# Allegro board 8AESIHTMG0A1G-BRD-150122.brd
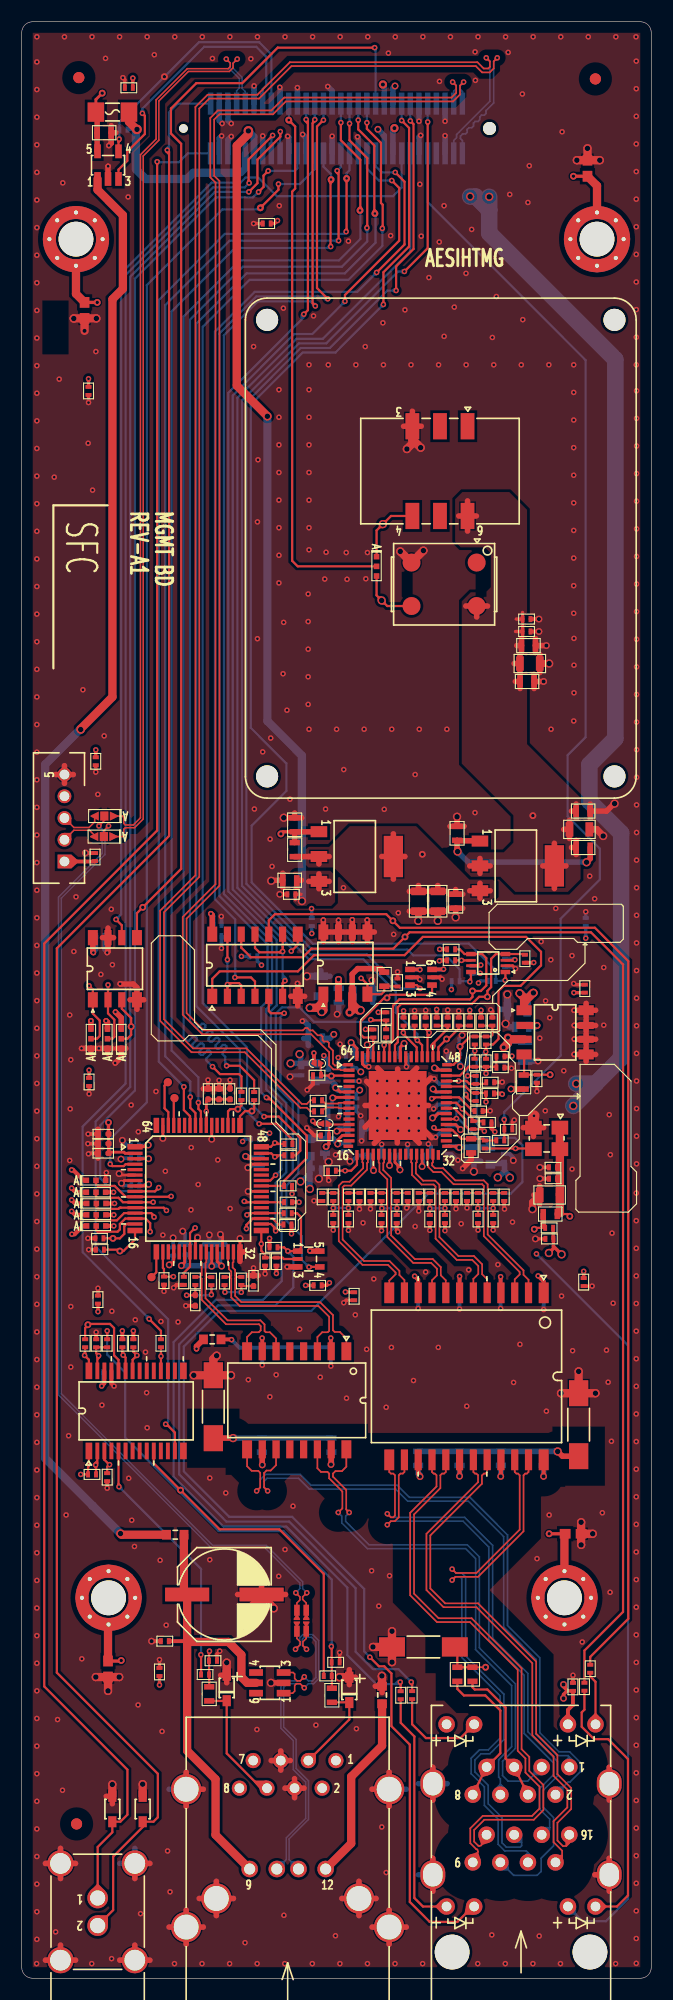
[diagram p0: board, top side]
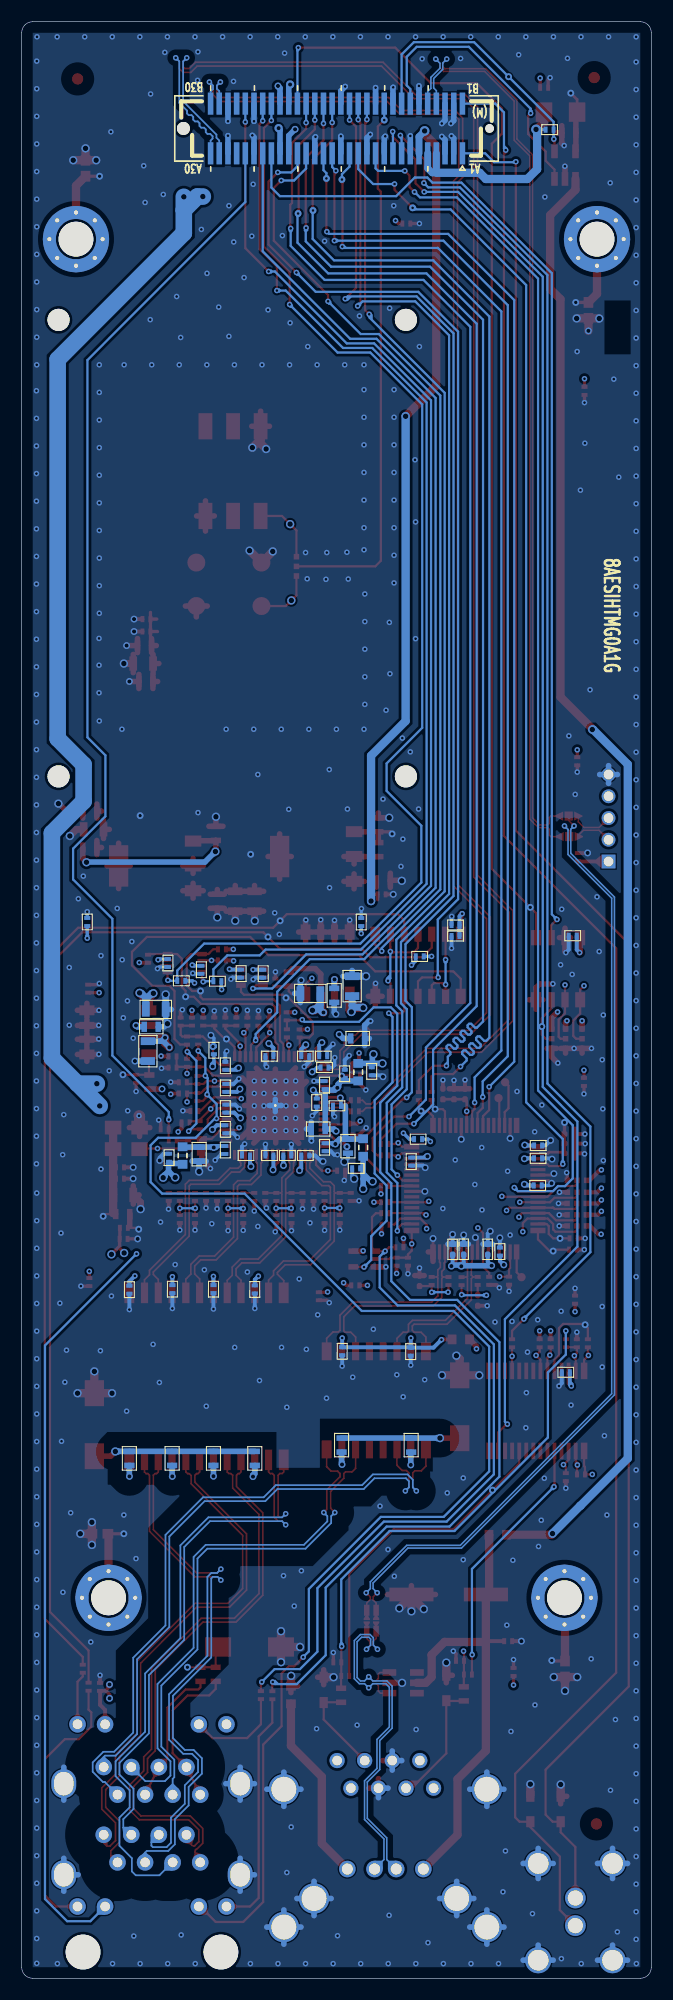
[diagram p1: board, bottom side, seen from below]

Outline 58 x 180 mm; copper layers: TOP, L2_GND, L3_VCC, BOTTOM. Coordinates in mm from the lower left corner of the outline.

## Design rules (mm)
net group RMIICRSDV: nets RMIICRSDV RMIICRSDV_R
net group RMIIRXD0: nets RMIIRXD0 RMIIRXD0_R
net group RMIIRXD1: nets RMIIRXD1 RMIIRXD1_R
net group RMIIRXER: nets RMIIRXER RMIIRXER_R
nets with their own width: min track width 0.254; nets 5V_IN

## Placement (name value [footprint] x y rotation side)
A1  3.5mm_8via  [A126_DG]  5 160 0 top
A2  3.5mm_8via  [A126_DG]  53 160 0 top
A3  3.5mm_8via  [A126_DG]  8 35 0 top
A4  3.5mm_8via  [A126_DG]  50 35 0 top
B1  Optics  [2B]  5.26 174.86 0 top
B2  Optics  [2B]  52.85 174.74 0 top
B3  Optics  [2B]  5.05 14.2 0 top
C1  1uF 6.3V  [C0402]  9.87 173.92 0 top
C2  0.1uF 16V  [C0603]  7.6 169.79 0 top
C3  0.1uF 16V***  [SJS_0603_PLANE]  52.12 166.52 90 top
C4  1uF 6.3V  [C0402]  22.57 161.43 0 top
C5  0.1uF 16V***  [SJS_0603_PLANE]  5.79 153.44 270 top
C6  1uF 6.3V  [C0402]  6.15 146.03 90 top
C7  0.1uF 16V  [C0402]  46.51 125.04 0 top
C8  0.1uF 16V  [C0402]  46.51 123.9 0 top
C9  1uF 25V  [C0603]  46.69 122.61 0 top
C10  22uF 6.3V  [C0805]  46.81 120.95 0 top
C11  0.1uF 16V  [C0603]  46.56 119.3 0 top
C12  1uF 6.3V  [C0402]  6.82 111.96 90 top
C13  0.1uF 16V  [C0603]  51.72 107.38 0 top
C14  22uF 6.3V  [C0805]  51.38 105.7 0 top
C15  0.1uF 16V  [C0402]  6.76 103.15 90 top
C16  1uF 25V  [C0603]  24.69 101.02 180 top
C17  0.1uF 16V  [C0402]  24.84 99.72 180 top
C18  22uF 6.3V  [C0805]  36.55 99.09 270 top
C19  22uF 6.3V  [C0805]  38.33 99.09 270 top
C20  0.1uF 16V  [C0603]  39.98 99.09 270 top
C21  0.1uF 16V  [C0402]  51.88 91.04 270 top
C22  100P 50V  [C0402]  36.2 88.01 90 top
C23  ***0.1uF 16V  [C0402]  27.21 83.08 0 top
C24  1uF 6.3V  [C0402]  6.21 82.46 90 top
C25  10NF 50V  [C0402-HANK]  17.16 81.35 90 top
C26  2.2UF X5R 6.3V 20%  [C0402-HANK]  18.18 81.35 90 top
C27  0.1uF 16V  [C0402-HANK]  19.2 81.35 90 top
C28  10NF 50V  [C0402]  27.3 80.77 0 top
C29  10NF 50V  [C0402]  27.3 79.76 0 top
C30  2.2UF X5R 6.3V 20%  [C0402-HANK]  7.51 77.67 180 top
C31  ***0.1uF 16V  [C0402]  27.93 77.54 0 top
C32  10NF 50V  [C0402-HANK]  7.51 76.78 180 top
C33  0.1uF 16V  [C0402-HANK]  7.51 75.89 180 top
C34  0.1uF 16V***  [C0402]  48.94 74.61 180 top
C35  1000P 50V***  [C0402]  48.95 73.56 180 top
C36  22uF 6.3V***  [C0805]  48.64 72.06 180 top
C37  ***5pF 50V  [C0402]  27.69 71.88 270 top
C38  ***5pF 50V  [C0402]  31.11 71.88 270 top
C39  ***5pF 50V  [C0402]  32.13 71.88 270 top
C40  ***5pF 50V  [C0402]  35.56 71.88 270 top
C41  ***5pF 50V  [C0402]  36.58 71.88 270 top
C42  ***5pF 50V  [C0402]  40.01 71.88 270 top
C43  ***5pF 50V  [C0402]  41.02 71.88 270 top
C44  ***5pF 50V  [C0402]  44.45 71.88 270 top
C45  ***0.1uF 16V  [C0402]  28.7 69.85 270 top
C46  10NF 50V  [C0402]  30.1 69.85 270 top
C47  ***0.1uF 16V  [C0402]  33.15 69.85 270 top
C48  10NF 50V  [C0402]  34.54 69.85 270 top
C49  10NF 50V  [C0402]  37.59 69.85 270 top
C50  ***0.1uF 16V  [C0402]  38.99 69.85 270 top
C51  ***0.1uF 16V  [C0402]  42.04 69.85 270 top
C52  10NF 50V  [C0402]  43.43 69.85 270 top
C53  0.1uF 16V***  [C0402]  48.62 68.02 180 top
C54  0.1uF 16V  [C0402-HANK]  21.35 64.17 90 top
C55  0.1uF 16V  [C0402]  51.77 64.05 90 top
C56  0.1uF 16V  [C0402]  27.27 63.75 180 top
C57  0.1uF 16V  [C0402]  30.62 62.74 90 top
C58  1uF 6.3V  [C0402]  7.02 62.43 270 top
C59  0.1uF 16V  [C0402-HANK]  15.99 62.36 270 top
C60  0.1uF 16V  [C0402]  5.84 58.42 270 top
C61  0.1uF 16V  [C0402]  6.86 58.42 270 top
C62  1000pF 3KV  [C1808_3KV]  17.65 52.58 90 top
C63  CAP 1000P/250Vac  [C1808_3KV]  51.31 50.93 90 top
C64  0.1uF 16V  [C0402]  6.48 46.35 180 top
C65  0.1uF 16V  [C0402]  7.87 46.1 90 top
C66  0.1uF 16V***  [SJS_0603_PLANE]  50.8 40.89 0 top
C67  180UF 16V  [C8P3X8P3]  18.67 35.31 0 top
C68  0.1uF 16V  [C0402]  13.18 31.01 0 top
C69  1000pF 3KV  [C1808_3KV]  37.01 30.48 0 top
C70  ***1000P 50V  [C0402]  17.62 29.21 0 top
C71  ***1000P 50V  [C0402]  28.92 29.07 0 top
C72  1uF 6.3V  [C0402]  12.69 28.18 270 top
C73  0.1uF 16V***  [SJS_0603_PLANE]  7.95 28.45 270 top
C74  0.1uF 16V  [C0402]  50.78 26.81 90 top
C75  0.1uF 16V  [C0402]  51.96 97.18 270 bottom
C76  0.1uF 16V  [C0402]  26.72 97.17 270 bottom
C77  0.1uF 16V  [C0402]  18.03 96.9 0 bottom
C78  0.1u 16V  [C0402]  7.24 95.91 180 bottom
C79  0.1uF 16V  [C0402]  18.03 95.89 0 bottom
C80  0.1uF 16V  [C0402]  21.33 94.01 180 bottom
C81  0.1uF 16V  [C0402]  44.53 93.4 270 bottom
C82  1uF 6.3V  [C0402]  41.45 92.78 270 bottom
C83  0.1uF 16V  [C0402]  37.79 92.43 270 bottom
C84  0.1uF 16V  [C0402]  35.75 92.42 270 bottom
C85  22uF 6.3V  [C0805]  27.56 91.27 90 bottom
C86  22uF 6.3V  [C0805]  31.41 90.6 0 bottom
C87  1uF 10V  [C0603]  29.21 90.42 270 bottom
C88  22uF 6.3V  [C0805]  45.65 89.13 180 bottom
C89  1uF 10V  [C0603]  46.07 87.53 180 bottom
C90  10uF 6.3V  [C0603]  27.05 86.46 180 bottom
C91  1uF 6.3V  [C0402]  40.29 85.38 90 bottom
C92  22uF 6.3V  [C0805]  46.38 85.3 270 bottom
C93  0.1uF 16V  [C0402]  35.18 84.84 0 bottom
C94  1uF 6.3V  [C0402]  31.88 84.84 180 bottom
C95  1uF 6.3V  [C0402]  30.23 84.84 180 bottom
C96  1uF 6.3V  [C0402]  39.24 83.95 90 bottom
C97  1uF 6.3V  [C0402]  30.1 83.78 180 bottom
C98  1uF 6.3V  [C0402]  25.76 83.44 270 bottom
C99  0.1uF 16V  [C0402]  28.24 83.21 90 bottom
C100  0.1uF 16V  [C0402]  30.1 82.17 90 bottom
C101  1uF 6.3V  [C0402]  39.24 81.92 90 bottom
C102  1uF 6.3V  [C0402]  30.82 80.56 270 bottom
C103  0.1uF 16V  [C0402]  28.96 80.26 0 bottom
C104  1uF 6.3V  [C0402]  39.24 80.01 90 bottom
C105  10uF 6.3V  [C0603]  30.68 78.13 0 bottom
C106  0.1uF 16V  [C0402]  39.24 78.11 270 bottom
C107  0.1uF 16V  [C0402]  21.48 77.2 180 bottom
C108  0.1uF 16V  [C0402]  10.42 76.62 0 bottom
C109  10uF 6.3V  [C0603]  27.94 76.56 270 bottom
C110  0.1uF 16V  [C0402]  30.1 76.45 270 bottom
C111  1uF 6.3V  [C0402]  39.24 76.2 270 bottom
C112  10uF 6.3V  [C0603]  41.66 75.82 270 bottom
C113  1uF 6.3V  [C0402]  37.34 75.69 0 bottom
C114  1uF 6.3V  [C0402]  35.18 75.69 0 bottom
C115  1uF 6.3V  [C0402]  33.53 75.69 180 bottom
C116  1uF 6.3V  [C0402]  31.88 75.69 180 bottom
C117  1uF 6.3V  [C0402]  44.42 75.49 90 bottom
C118  0.1uF 16V  [C0402]  10.43 75.43 0 bottom
C119  0.1uF 16V  [C0402]  22.12 75.13 90 bottom
C120  1uF 6.3V  [C0402]  27.19 74.51 0 bottom
C121  0.1uF 16V  [C0402]  10.46 72.94 0 bottom
C122  0.1uF 16V  [C0402-HANK]  17.28 67.07 90 bottom
C123  2.2UF X5R 6.3V 20%  [C0402-HANK]  15.07 67.06 90 bottom
C124  10NF 50V  [C0402-HANK]  18.3 67.06 90 bottom
C125  0.1uF 16V  [C0402]  13.95 66.85 270 bottom
C126  0.1uF 16V  [C0402]  44.12 63.4 270 bottom
C127  0.1uF 16V  [C0402]  40.34 63.4 270 bottom
C128  0.1uF 16V  [C0402]  36.53 63.37 270 bottom
C129  0.1uF 16V  [C0402]  48.08 63.35 270 bottom
C130  0.1uF 16V  [C0402]  28.48 57.68 270 bottom
C131  0.1uF 16V  [C0402]  22.16 57.65 270 bottom
C132  0.1uF 16V  [C0402]  7.87 55.75 180 bottom
D1  SRV05-4  [SOT_26]  22.86 27.18 90 top
D2  GBLC24C  [SOD_323]  18.88 26.71 270 top
D3  GBLC24C  [SOD_323]  30.18 26.53 270 top
D4  GBLC03C  [SOD_323N]  8.35 15.57 90 top
D5  GBLC03C  [SOD_323N]  11.14 15.57 90 top
F1  1.5A/63V  [FUSE_1206]  8.36 171.69 0 top
J1  33R 5% 1/16W  [JP3_0402]  32.69 129.9 270 top
J2  1K 5% 1/16W  [JP3_0402]  6.38 86.44 90 top
J3  1K 5% 1/16W  [JP3_0402]  7.9 86.44 90 top
J4  1K 5% 1/16W  [JP3_0402]  9.17 86.44 90 top
J5  1K 5% 1/16W  [JP3_0402]  6.84 73.41 0 top
J6  1K 5% 1/16W  [JP3_0402]  6.84 72.31 0 top
J7  1K 5% 1/16W  [JP3_0402]  6.87 71.28 0 top
J8  1K 5% 1/16W  [JP3_0402]  6.87 70.24 0 top
J9  1K 5% 1/16W  [JP3_0402]  6.86 69.21 0 top
J10  TE# 3-5177986-2  [C_5179029_2]  29 170.18 0 bottom
JP1  HEADER1* 5P=2.0 mm  [P200_5_2P0]  3.94 102.74 90 top
L1  40ohm/100MHZ 0.4A***  [L0603]  48.69 70.31 0 top
L2  HCB1608KF-601T10  [L2_LQW18]  17.55 58.78 0 top
L3  HCB1608KF-601T10  [L2_LQW18]  14.15 40.8 180 top
L4  BEAD 600OHM/ 100MHZ 25%  [L0603]  17.27 26.16 270 top
L5  HCB1608KF-601T10  [L2_LQW18]  33.2 26.06 270 top
L6  BEAD 600OHM/ 100MHZ 25%  [L0603]  28.57 26.04 270 top
L7  HCB1608KF-601T10  [L2_LQW18]  27 83.36 270 bottom
L8  HCB1608KF-601T10  [L2_LQW18]  26.54 76.43 90 bottom
L9  HCB1608KF-601T10  [L2_LQW18]  43.18 75.69 90 bottom
N1  0ohm  [0_OHM_3PIN]  7.61 106.92 180 top
N2  0ohm  [0_OHM_3PIN]  7.57 105.03 180 top
N3  0ohm  [0_OHM_2PIN]  27.24 84.18 180 top
N4  0ohm  [0_OHM_2PIN]  27.93 78.63 180 top
N5  0ohm***  [0_OHM_2PIN]  25.35 32.89 270 top
N6  0ohm***  [0_OHM_2PIN]  26.21 32.89 270 top
NOREF  ***  []  1.91 154.36 270 top
NOREF#2  -  []  60.71 180.09 0 top
NOREF#3  -  []  0 0 0 top
NOREF#4  -  []  2.92 135.51 270 top
NOREF#5  -  []  4.39 116.99 90 top
NOREF#6  -  []  12.27 135.13 270 top
P1  Plastic Top Cover  [OSCD5_OCXO_131_COVER]  38.61 131.57 270 top
P2  AJ-091-21-F-R4-N4-5G  [PHJ8X1X2_LED_D]  52.35 2.41 180 top
P3  PHJ8 + USB  [PHJ8_SHIE_USB_A]  31.07 7.34 0 top
P4  MiniBNC1x2 MDB-960  [BNC_MDB_960]  10.42 1.66 270 top
R1  1.1K 1% 1/10W  [R0603]  25.15 106.12 90 top
R2  392 1% 1/10W  [R0603]  40.11 105.33 90 top
R3  240 5% 1/10W  [R0603]  51.72 104.03 0 top
R4  240 5% 1/10W  [R0603]  25.15 103.84 90 top
R5  3.3K 5% 1/16W  [R0402]  39.56 94.66 0 top
R6  3.3K 5% 1/16W  [R0402]  46.36 93.8 90 top
R7  3.3K 5% 1/16W  [R0402]  39.56 93.64 180 top
R8  5.11K 1% 1/10W  [R0603]  33.4 91.92 270 top
R9  10K 1% 1/16W  [R0402]  34.62 91.61 90 top
R10  4.7K 1% 1/16W  [R0402]  33.59 88.5 270 top
R11  4.7K 1% 1/16W  [R0402]  35.18 88.01 90 top
R12  1K 1% 1/16W  [R0402]  37.21 88.01 90 top
R13  ***4.7K 1% 1/16W  [R0402]  38.23 88.01 270 top
R14  1K 1% 1/16W  [R0402]  39.24 88.01 90 top
R15  ***1K 1% 1/16W  [R0402]  40.26 88.01 90 top
R16  4.7K 1% 1/16W  [R0402]  41.27 88.01 270 top
R17  ***0ohm 5% 1/16W  [R0402]  42.32 88.01 270 top
R18  ***0ohm 5% 1/16W  [R0402]  43.36 88.01 270 top
R19  0ohm 5% 1/16W  [R0402]  33.57 86.94 90 top
R20  4.7K 1% 1/16W  [R0402]  32.39 86.92 90 top
R21  ***0ohm 5% 1/16W  [R0402]  42.77 86.27 270 top
R22  0ohm 5% 1/16W  [R0402]  41.74 86.27 270 top
R23  ***0ohm 5% 1/16W  [R0402]  44.11 84.81 180 top
R24  ***0ohm 5% 1/16W  [R0402]  41.72 84.22 90 top
R25  ***0ohm 5% 1/16W  [R0402]  42.77 84.22 90 top
R26  0ohm 5% 1/16W  [R0402]  44.1 83.78 180 top
R27  10.5K 1% 1/16W  [R0402]  47.46 82.76 270 top
R28  ***0ohm 5% 1/16W  [R0402]  41.82 82.65 90 top
R29  22.6K 1% 1/10W  [R0603]  46.24 82.45 90 top
R30  0ohm 5% 1/16W  [R0402]  43.16 82.43 180 top
R31  ***0ohm 5% 1/16W  [R0402]  43.14 81.4 180 top
R32  33 1% 1/16W  [R0402]  20.24 81.17 90 top
R33  33 1% 1/16W  [R0402]  21.41 81.16 90 top
R34  0ohm 5% 1/16W  [R0402]  41.83 81.08 270 top
R35  0ohm 5% 1/16W  [R0402]  42.09 79.78 180 top
R36  ***0ohm 5% 1/16W  [R0402]  42.91 78.74 180 top
R37  0ohm 5% 1/16W  [R0402]  41.6 78.49 270 top
R38  ***49.9 1% 1/16W  [R0402]  44.83 78.11 180 top
R39  33 1% 1/16W  [R0402]  44.09 77.09 180 top
R40  33 1% 1/16W  [R0402]  24.57 76.76 0 top
R41  33 1% 1/16W***  [R0402]  42.67 76.71 90 top
R42  220 1% 1/10W***  [R0603]  41.4 76.58 270 top
R43  33 1% 1/16W  [R0402]  24.56 75.71 0 top
R44  4.99K 1% 1/16W  [R0402]  28.57 74.3 0 top
R45  1.5K 5% 1/16W  [R0402]  24.54 72.9 0 top
R46  49.9 1% 1/16W  [R0402]  28.7 71.88 270 top
R47  49.9 1% 1/16W  [R0402]  30.1 71.88 90 top
R48  49.9 1% 1/16W  [R0402]  33.15 71.88 270 top
R49  49.9 1% 1/16W  [R0402]  34.54 71.88 90 top
R50  49.9 1% 1/16W  [R0402]  37.59 71.88 270 top
R51  49.9 1% 1/16W  [R0402]  38.99 71.88 90 top
R52  49.9 1% 1/16W  [R0402]  42.04 71.88 270 top
R53  49.9 1% 1/16W  [R0402]  43.43 71.88 90 top
R54  10K 1% 1/16W  [R0402]  24.54 71.4 0 top
R55  0ohm 5% 1/16W  [R0402]  24.51 70.38 0 top
R56  4.7K 5% 1/16W  [R0402]  24.49 69.34 180 top
R57  2.2 ohm 5% 1/16W***  [R0402]  48.59 69.04 180 top
R58  1K 5% 1/16W  [R0402]  7.16 68.07 0 top
R59  4.7K 5% 1/16W  [R0402]  23.2 67.24 0 top
R60  1K 5% 1/16W  [R0402]  7.21 67.03 0 top
R61  1K 5% 1/16W  [R0402]  22.42 65.93 270 top
R62  4.7K 5% 1/16W  [R0402]  23.46 65.93 90 top
R63  1K 5% 1/16W  [R0402]  13.11 64.18 90 top
R64  1.27K 1% 1/16W  [R0402]  14.93 64.16 90 top
R65  49.9 1% 1/16W  [R0402]  15.99 64.15 270 top
R66  49.9 1% 1/16W  [R0402]  20.23 64.15 270 top
R67  49.9 1% 1/16W  [R0402]  18.68 64.15 270 top
R68  49.9 1% 1/16W  [R0402]  17.48 64.14 270 top
R69  4.7K 5% 1/16W  [R0402]  7.87 58.42 270 top
R70  4.7K 5% 1/16W  [R0402]  9.27 58.42 90 top
R71  4.7K 5% 1/16W  [R0402]  10.29 58.42 90 top
R72  33 1% 1/16W  [R0402]  12.83 58.42 270 top
R73  75 1% 1/10W  [R0603]  40.13 27.97 270 top
R74  75 1% 1/10W  [R0603]  41.53 27.97 270 top
R75  33 1% 1/16W  [R0402]  16.89 27.94 0 top
R76  33 1% 1/16W  [R0402]  28.19 27.81 0 top
R77  120 1% 1/16W  [R0402]  51.84 26.82 270 top
R78  120 1% 1/16W  [R0402]  52.37 28.47 270 top
R79  120 1% 1/16W  [R0402]  35.96 26.05 270 top
R80  120 1% 1/16W  [R0402]  34.91 26.04 270 top
R81  20K 5% 1/16W  [R0402]  9.37 170.07 180 bottom
R82  1K 5% 1/16W  [R0402]  43.3 91.76 180 bottom
R83  1K 5% 1/16W  [R0402]  39.97 91.73 180 bottom
R84  75 1% 1/10W  [R0603]  28.53 49.05 90 bottom
R85  75 1% 1/10W  [R0603]  22.12 49.05 90 bottom
R86  75 1% 1/10W  [R0603]  48.08 47.83 90 bottom
R87  75 1% 1/10W  [R0603]  44.15 47.83 90 bottom
R88  75 1% 1/10W  [R0603]  40.34 47.83 90 bottom
R89  75 1% 1/10W  [R0603]  36.53 47.83 90 bottom
T1  G24101MK  [SOP24_1P27_16]  40.97 55.38 180 top
T2  LH16125SN  [SOP16_1P27_9P4_A]  25.33 53.17 180 top
TP1  TP  [T30]  13.46 82.44 0 top
TP2  TP  [T30]  14.07 80.98 0 top
TP3  TP  [T30]  11.96 64.5 0 top
U1  TPS2051B  [SOT_25]  7.95 166.81 0 top
U2  RT9164APG  [SOT_223]  30.86 103.2 270 top
U3  RT9164APG  [SOT_223]  45.69 102.34 270 top
U4  TXS0102DCUR  [SOP8_0P5_3P1]  42.97 93.4 90 top
U5  RT9183  [SOP8_1P27_6]  29.82 93.4 0 top
U6  SN74LVC14ADR  [SOP14_1P27_6]  21.49 93.2 0 top
U7  AT24C02D-SSHM-T  [SOP8_1P27_6]  8.59 92.88 0 top
U8  74AVC1T45GW  [SOT_363]  36.79 92.09 270 top
U9  RT9183  [SOP8_1P27_6]  49.14 87.02 270 top
U10  88E1112-C2-NNC1C000  [LCC64_9X9_0P5_C]  34.63 80.29 0 top
U11  BCM5221A4KPTG  [QFP64_12X12_0P5]  16.26 72.64 270 top
U12  SN74AHC1G32DCKR  [SOT_353]  26.44 66.17 270 top
U13  ZT3243LEEA(RS232)  [SOP28_0P65_7P8]  10.54 52.2 0 top
U14  F4P-2012  [L4_2012]  25.78 32.89 270 top
X1  ***P5473LF_25M_OCXO  [OSC6_P5473LF]  38.53 138.66 180 top
X2  M5859LF-C  [OSC4_M5769LF]  38.91 128.24 180 top
X3  25.000000M 3.3V***  [OSC4_SCO_A571]  48.36 77.27 180 top

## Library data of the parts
A1-A4 = SCREW HOLE_6: Tolerance: ***; User Part Number: ***; room: SCREW
B1-B3 = Optics_solder: Tolerance: ***; User Part Number: ***
C1 C4 C6 C12 C21 C24 C27 C33 C34 C53-C61 C64 C65 C72 C74-C77 C79 C80 C107 C108 C118 C119 C121 C122 C125-C129 C132 = CAP_NP: Tolerance: ***; User Part Number: ***; room: SW2
C2 C3 C5 C7-C11 C13-C20 C22 C23 C25 C26 C28-C32 C35-C52 C62 C63 C66 C68-C71 C73 C78 C81-C106 C109-C117 C120 C123 C124 C130 C131 = CAP_NP: Tolerance: ***; User Part Number: ***
C67 = CAP: Tolerance: ***; User Part Number: ***
D1 = SRV05: Tolerance: ***; User Part Number: ***
D2 D3 = SCHOTTKY: Tolerance: ***; User Part Number: ***
D4 D5 = SCHOTTKY_0: Tolerance: ***; User Part Number: ***
F1 = FUSE: Tolerance: ***; User Part Number: ***
J1-J9 = JP3_0603: Tolerance: ***; User Part Number: ***
J10 = AMP2X20_0: Tolerance: ***; User Part Number: ***
JP1 = JP5_1: Tolerance: ***; User Part Number: ***
L1-L3 L5 L7-L9 = INDUCTOR: Tolerance: ***; User Part Number: ***
L4 L6 = INDUCTOR_4: Tolerance: ***; User Part Number: ***; room: RS232
N1 N2 = JP3_0603_0OHM: Tolerance: ***; User Part Number: ***
N3-N6 = R_0OHM: Tolerance: ***; User Part Number: ***
P1 = Test PAD_0: Tolerance: ***; User Part Number: ***
P2 = PHJ8X1X2_LED2_1: Tolerance: ***; User Part Number: ***
P3 = PHJ8_SHIE_LED_USB_1: Tolerance: ***; User Part Number: ***
P4 = MDB_960: Tolerance: ***; User Part Number: ***
R1-R31 R34-R39 R41 R42 R44-R57 R59 R62 R64-R89 = R: Tolerance: ***; User Part Number: ***
R32 R33 R40 R43 = R: Tolerance: ***; User Part Number: ***; signal model: R_R0402_33_1%_1/16W_33_1%_1/16W
R58 R60 R61 R63 = R: Tolerance: ***; User Part Number: ***; room: XLR716
T1 = H5004: Tolerance: ***; User Part Number: ***
T2 = FL1012_0: Tolerance: ***; User Part Number: ***
TP1-TP3 = JP1_0: Tolerance: ***; User Part Number: ***; room: DDR_DIV
U1 = TPS2051B: Tolerance: ***; User Part Number: ***
U2 U3 = 7812_0: Tolerance: ***; User Part Number: ***
U4 = TXS0102: Tolerance: ***; User Part Number: ***
U5 U9 = RT9183HCS_0: Tolerance: ***; User Part Number: ***
U6 = 74LS04: Tolerance: ***; User Part Number: ***
U7 = AT24C512: Tolerance: ***; User Part Number: ***
U8 = 74AVC1T45GW: Tolerance: ***; User Part Number: ***
U10 = 88E1112_0: Tolerance: ***; User Part Number: ***
U11 = BCM5221_0: Tolerance: ***; User Part Number: ***
U12 = ELM7S86: Tolerance: ***; User Part Number: ***
U13 = MAX3243: Tolerance: ***; User Part Number: ***; room: RS232
U14 = F4P_2012: Tolerance: ***; User Part Number: ***
X1 = YN8960001_6: Tolerance: ***; User Part Number: ***
X2 = OSC_SMD_9: Tolerance: ***; User Part Number: ***
X3 = OSC_SMD: Tolerance: ***; User Part Number: ***

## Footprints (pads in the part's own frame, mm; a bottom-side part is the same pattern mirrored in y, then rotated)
0_OHM_2PIN
  custom 0.127x0.127 smd: 1(-0.318,0) 2(0.318,0)
0_OHM_3PIN
  custom 0.191x0.191 smd: 1(-0.889,0) 3(0.889,0)
  rect 0.762x0.838 smd: 2(0,0)
2B
  round 1.016 smd: 1(0,0) 2(0,0)
A126_DG
  round 3.2 hole 3.2 unplated: (0,0)
  round 1.194 hole 0.381: 2(1.732,1.732) 3(-1.732,1.732) 4(-1.732,-1.732) 5(1.732,-1.732) 6(0,2.451) 7(0,-2.451) 8(-2.451,0) 9(2.451,0)
BNC_MDB_960
  round 1.905 hole 1.397: 1(-5.72,-3.425) 2(-3.18,-3.425)
  round 2.413 hole 1.905: 3(-8.9,0) 4(0,0) 5(-8.9,-6.85) 6(0,-6.85)
C8P3X8P3
  rect 4.064x1.27 smd: 1(-3.429,0) 2(3.429,0)
C0402
  rect 0.356x0.559 smd: 1(-0.368,0) 2(0.368,0)
C0402-HANK
  custom 0.127x0.127 smd: 1(-0.483,0) 2(0.483,0)
C0603
  rect 0.508x0.94 smd: 1(-0.648,0) 2(0.648,0)
C0805
  rect 0.711x1.321 smd: 1(-0.914,0) 2(0.914,0)
C1808_3KV
  rect 2.388x1.778 smd: 1(-2.896,0) 2(2.896,0)
C_5179029_2
  round 0.787 hole 0.787 unplated: (-14.1,0)
  round 1.194 hole 1.194 unplated: (14.1,0)
  rect 0.508x2.032 smd: A1(-11.6,2.286) A2(-10.8,2.286) A3(-10,2.286) A4(-9.2,2.286) A5(-8.4,2.286) A6(-7.6,2.286) A7(-6.8,2.286) A8(-6,2.286) A9(-5.2,2.286) A10(-4.4,2.286) A11(-3.6,2.286) A12(-2.8,2.286) A13(-2,2.286) A14(-1.2,2.286) A15(-0.4,2.286) A16(0.4,2.286) A17(1.2,2.286) A18(2,2.286) A19(2.8,2.286) A20(3.6,2.286) A21(4.4,2.286) A22(5.2,2.286) A23(6,2.286) A24(6.8,2.286) A25(7.6,2.286) A26(8.4,2.286) A27(9.2,2.286) A28(10,2.286) A29(10.8,2.286) A30(11.6,2.286) B1(-11.6,-2.286) B2(-10.8,-2.286) B3(-10,-2.286) B4(-9.2,-2.286) B5(-8.4,-2.286) B6(-7.6,-2.286) B7(-6.8,-2.286) B8(-6,-2.286) B9(-5.2,-2.286) B10(-4.4,-2.286) B11(-3.6,-2.286) B12(-2.8,-2.286) B13(-2,-2.286) B14(-1.2,-2.286) B15(-0.4,-2.286) B16(0.4,-2.286) B17(1.2,-2.286) B18(2,-2.286) B19(2.8,-2.286) B20(3.6,-2.286) B21(4.4,-2.286) B22(5.2,-2.286) B23(6,-2.286) B24(6.8,-2.286) B25(7.6,-2.286) B26(8.4,-2.286) B27(9.2,-2.286) B28(10,-2.286) B29(10.8,-2.286) B30(11.6,-2.286)
FUSE_1206
  rect 1.524x1.778 smd: 1(-1.524,0) 2(1.524,0)
JP3_0402
  rect 0.508x0.508 smd: 1(-0.889,0) 2(0,0) 3(0.889,0)
L2_LQW18
  rect 0.813x0.889 smd: 1(-0.806,0) 2(0.806,0)
L4_2012
  rect 1.016x0.508 smd: 1(-0.965,0.432) 2(0.965,0.432) 3(0.965,-0.432) 4(-0.965,-0.432)
L0603
  rect 0.508x0.94 smd: 1(-0.648,0) 2(0.648,0)
LCC64_9X9_0P5_C
  rect 0.889x0.305 smd: 1(-4.483,3.75) 16(-4.483,-3.75) 33(4.483,-3.75) 48(4.483,3.75)
  rect 1.016x0.305 smd: 2(-4.483,3.25) 3(-4.483,2.75) 4(-4.483,2.25) 5(-4.483,1.75) 6(-4.483,1.25) 7(-4.483,0.75) 8(-4.483,0.25) 9(-4.483,-0.25) 10(-4.483,-0.75) 11(-4.483,-1.25) 12(-4.483,-1.75) 13(-4.483,-2.25) 14(-4.483,-2.75) 15(-4.483,-3.25) 34(4.483,-3.25) 35(4.483,-2.75) 36(4.483,-2.25) 37(4.483,-1.75) 38(4.483,-1.25) 39(4.483,-0.75) 40(4.483,-0.25) 41(4.483,0.25) 42(4.483,0.75) 43(4.483,1.25) 44(4.483,1.75) 45(4.483,2.25) 46(4.483,2.75) 47(4.483,3.25)
  rect 0.305x0.889 smd: 17(-3.75,-4.483) 32(3.75,-4.483) 49(3.75,4.483) 64(-3.75,4.483)
  rect 0.305x1.016 smd: 18(-3.25,-4.483) 19(-2.75,-4.483) 20(-2.25,-4.483) 21(-1.75,-4.483) 22(-1.25,-4.483) 23(-0.75,-4.483) 24(-0.25,-4.483) 25(0.25,-4.483) 26(0.75,-4.483) 27(1.25,-4.483) 28(1.75,-4.483) 29(2.25,-4.483) 30(2.75,-4.483) 31(3.25,-4.483) 50(3.25,4.483) 51(2.75,4.483) 52(2.25,4.483) 53(1.75,4.483) 54(1.25,4.483) 55(0.75,4.483) 56(0.25,4.483) 57(-0.25,4.483) 58(-0.75,4.483) 59(-1.25,4.483) 60(-1.75,4.483) 61(-2.25,4.483) 62(-2.75,4.483) 63(-3.25,4.483)
  rect 5.334x6.35 hole 0.254: 65(0,0)
OSC4_M5769LF
  round 1.651 smd: 1(-3,-2) 2(3,-2) 3(3,2) 4(-3,2)
OSC4_SCO_A571
  rect 1.524x1.27 smd: 1(-1.219,-0.991) 2(1.219,-0.991) 3(1.219,0.991) 4(-1.219,0.991)
OSC6_P5473LF
  rect 1.27x2.413 smd: 1(-2.54,-4.128) 2(0,-4.128) 3(2.54,-4.128) 4(2.54,4.128) 5(0,4.128) 6(-2.54,4.128)
OSCD5_OCXO_131_COVER
  round 2.032 hole 2.032 unplated: (-21,16) (-21,-16) (21,16) (21,-16)
P200_5_2P0
  rect 1.27x1.27 hole 0.889: 1(0,0)
  round 1.27 hole 0.889: 2(2,0) 3(4,0) 4(6,0) 5(8,0)
PHJ8_SHIE_USB_A
  round 1.397 hole 0.889: 1(-2.125,12.69) 2(-3.395,10.15) 3(-4.665,12.69) 4(-5.935,10.15) 5(-7.205,12.69) 6(-8.475,10.15) 7(-9.745,12.69) 8(-11.015,10.15)
  round 1.524 hole 1.016: 9(-10.07,2.71) 10(-7.57,2.71) 11(-5.57,2.71) 12(-3.07,2.71)
  round 2.794 hole 2.286: 13(-15.92,-2.63) 14(2.78,-2.63) 15(-15.92,10.05) 16(2.78,10.05) 17(-13.14,0) 18(0,0)
PHJ8X1X2_LED_D
  round 3.2 hole 3.2 unplated: (0,0) (12.7,0)
  round 1.524 hole 0.889: 1(1.905,-17.02) 2(3.175,-14.48) 3(4.445,-17.02) 4(5.715,-14.48) 5(6.985,-17.02) 6(8.255,-14.48) 7(9.525,-17.02) 8(10.795,-14.48) 9(10.795,-8.25) 10(9.525,-10.79) 11(8.255,-8.25) 12(6.985,-10.79) 13(5.715,-8.25) 14(4.445,-10.79) 15(3.175,-8.25) 16(1.905,-10.79) 17(10.67,-20.95) 18(13.21,-20.95) 19(-0.51,-20.95) 20(2.03,-20.95) 21(10.67,-4.19) 22(13.21,-4.19) 23(-0.51,-4.19) 24(2.03,-4.19)
  oval 2.286x2.667 hole 1.778x2.159: 25(-1.775,-15.49) 26(14.475,-15.49) 27(-1.775,-7.11) 28(14.475,-7.11)
QFP64_12X12_0P5
  rect 0.508x1.397 smd: 1(-3.852,-5.817) 16(3.852,-5.817) 33(3.852,5.817) 48(-3.852,5.817)
  rect 0.305x1.397 smd: 2(-3.25,-5.817) 3(-2.75,-5.817) 4(-2.25,-5.817) 5(-1.75,-5.817) 6(-1.25,-5.817) 7(-0.75,-5.817) 8(-0.25,-5.817) 9(0.25,-5.817) 10(0.75,-5.817) 11(1.25,-5.817) 12(1.75,-5.817) 13(2.25,-5.817) 14(2.75,-5.817) 15(3.25,-5.817) 34(3.25,5.817) 35(2.75,5.817) 36(2.25,5.817) 37(1.75,5.817) 38(1.25,5.817) 39(0.75,5.817) 40(0.25,5.817) 41(-0.25,5.817) 42(-0.75,5.817) 43(-1.25,5.817) 44(-1.75,5.817) 45(-2.25,5.817) 46(-2.75,5.817) 47(-3.25,5.817)
  rect 1.397x0.508 smd: 17(5.817,-3.852) 32(5.817,3.852) 49(-5.817,3.852) 64(-5.817,-3.852)
  rect 1.397x0.305 smd: 18(5.817,-3.25) 19(5.817,-2.75) 20(5.817,-2.25) 21(5.817,-1.75) 22(5.817,-1.25) 23(5.817,-0.75) 24(5.817,-0.25) 25(5.817,0.25) 26(5.817,0.75) 27(5.817,1.25) 28(5.817,1.75) 29(5.817,2.25) 30(5.817,2.75) 31(5.817,3.25) 50(-5.817,3.25) 51(-5.817,2.75) 52(-5.817,2.25) 53(-5.817,1.75) 54(-5.817,1.25) 55(-5.817,0.75) 56(-5.817,0.25) 57(-5.817,-0.25) 58(-5.817,-0.75) 59(-5.817,-1.25) 60(-5.817,-1.75) 61(-5.817,-2.25) 62(-5.817,-2.75) 63(-5.817,-3.25)
R0402
  rect 0.356x0.559 smd: 1(-0.368,0) 2(0.368,0)
R0603
  rect 0.508x0.94 smd: 1(-0.648,0) 2(0.648,0)
SJS_0603_PLANE
  rect 0.991x0.889 smd: 1(-0.737,0) 2(0.737,0)
SOD_323
  rect 1.016x0.762 smd: 1(-1.168,0) 2(1.168,0)
SOD_323N
  rect 1.016x0.762 smd: 1(-1.168,0) 2(1.168,0)
SOP8_0P5_3P1
  rect 0.406x0.889 smd: 1(-0.826,-1.587) 4(0.826,-1.587) 5(0.826,1.587) 8(-0.826,1.587)
  rect 0.254x0.889 smd: 2(-0.25,-1.587) 3(0.25,-1.587) 6(0.25,1.587) 7(-0.25,1.587)
SOP8_1P27_6
  rect 0.914x1.397 smd: 1(-2.032,-2.857) 4(2.032,-2.857) 5(2.032,2.857) 8(-2.032,2.857)
  rect 0.66x1.397 smd: 2(-0.635,-2.857) 3(0.635,-2.857) 6(0.635,2.857) 7(-0.635,2.857)
SOP14_1P27_6
  rect 0.914x1.397 smd: 1(-3.937,-2.857) 7(3.937,-2.857) 8(3.937,2.857) 14(-3.937,2.857)
  rect 0.66x1.397 smd: 2(-2.54,-2.857) 3(-1.27,-2.857) 4(0,-2.857) 5(1.27,-2.857) 6(2.54,-2.857) 9(2.54,2.857) 10(1.27,2.857) 11(0,2.857) 12(-1.27,2.857) 13(-2.54,2.857)
SOP16_1P27_9P4_A
  rect 0.914x1.651 smd: 1(-4.572,-4.508) 8(4.572,-4.508) 9(4.572,4.508) 16(-4.572,4.508)
  rect 0.66x1.651 smd: 2(-3.175,-4.508) 3(-1.905,-4.508) 4(-0.635,-4.508) 5(0.635,-4.508) 6(1.905,-4.508) 7(3.175,-4.508) 10(3.175,4.508) 11(1.905,4.508) 12(0.635,4.508) 13(-0.635,4.508) 14(-1.905,4.508) 15(-3.175,4.508)
SOP24_1P27_16
  rect 0.914x1.905 smd: 1(-7.112,-7.684) 12(7.112,-7.684) 13(7.112,7.684) 24(-7.112,7.684)
  rect 0.66x1.905 smd: 2(-5.715,-7.684) 3(-4.445,-7.684) 4(-3.175,-7.684) 5(-1.905,-7.684) 6(-0.635,-7.684) 7(0.635,-7.684) 8(1.905,-7.684) 9(3.175,-7.684) 10(4.445,-7.684) 11(5.715,-7.684) 14(5.715,7.684) 15(4.445,7.684) 16(3.175,7.684) 17(1.905,7.684) 18(0.635,7.684) 19(-0.635,7.684) 20(-1.905,7.684) 21(-3.175,7.684) 22(-4.445,7.684) 23(-5.715,7.684)
SOP28_0P65_7P8
  rect 0.61x1.524 smd: 1(-4.352,-3.683) 14(4.352,-3.683) 15(4.352,3.683) 28(-4.352,3.683)
  rect 0.356x1.524 smd: 2(-3.575,-3.683) 3(-2.925,-3.683) 4(-2.275,-3.683) 5(-1.625,-3.683) 6(-0.975,-3.683) 7(-0.325,-3.683) 8(0.325,-3.683) 9(0.975,-3.683) 10(1.625,-3.683) 11(2.275,-3.683) 12(2.925,-3.683) 13(3.575,-3.683) 16(3.575,3.683) 17(2.925,3.683) 18(2.275,3.683) 19(1.625,3.683) 20(0.975,3.683) 21(0.325,3.683) 22(-0.325,3.683) 23(-0.975,3.683) 24(-1.625,3.683) 25(-2.275,3.683) 26(-2.925,3.683) 27(-3.575,3.683)
SOT_25
  rect 0.61x1.27 smd: 1(-0.965,-1.27) 2(0,-1.27) 3(0.965,-1.27) 4(0.965,1.27) 5(-0.965,1.27)
SOT_26
  rect 0.61x1.27 smd: 1(-0.95,-1.27) 2(0,-1.27) 3(0.95,-1.27) 4(0.95,1.27) 5(0,1.27) 6(-0.95,1.27)
SOT_223
  rect 1.016x1.524 smd: 1(-2.286,-3.48) 2(0,-3.48) 3(2.286,-3.48)
  rect 3.81x1.778 smd: 4(0,3.378)
SOT_353
  rect 0.508x0.889 smd: 1(-0.724,-1.016) 3(0.724,-1.016) 4(0.724,1.016) 5(-0.724,1.016)
  rect 0.356x0.889 smd: 2(0,-1.016)
SOT_363
  rect 0.508x0.889 smd: 1(-0.724,-1.016) 3(0.724,-1.016) 4(0.724,1.016) 6(-0.724,1.016)
  rect 0.356x0.889 smd: 2(0,-1.016) 5(0,1.016)
T30
  round 0.762 smd: 1(0,0)

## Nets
3.3V_OCXO: C7.1 C8.1 C9.1 C10.1 C11.1 C13.1 C14.1 R3.1 U3.2(VOUT#2) U3.4(VOUT#4) X1.6(VCC) X2.4(VCC)
5V_IN: C2.1 F1.1 U1.5(VIN)
7V_OCXO: C18.1 C19.1 C20.1 R4.1 U2.2(VOUT#2) U2.4(VOUT#4) U3.3(VIN)
GND: C1.1 C2.2 C3.2 C4.1 C5.2 C6.1 C7.2 C8.2 C9.2 C10.2 C11.2 C12.1 C13.2 C14.2 C15.2 C16.2 C17.2 C18.2 C19.2 C20.2 C21.1 C22.2 C23.1 C24.1 C25.2 C26.2 C27.2 C30.2 C31.1 C32.2 C33.2 C34.2 C35.2 C36.2 C37.2 C38.2 C39.2 C40.2 C41.2 C42.2 C43.2 C44.2 C45.2 C46.2 C47.2 C48.2 C49.2 C50.2 C51.2 C52.2 C53.2 C54.2 C55.1 C57.1 C58.1 C59.2 C61.1 C62.2 C63.2 C65.1 C66.2 C67.2 C68.1 C69.1 C70.2 C71.2 C72.1 C73.2 C74.2 C75.1 C76.1 C77.2 C78.1 C79.2 C81.2 C82.2 C83.2 C84.2 C85.2 C86.2 C87.2 C88.2 C89.2 C90.2 C91.2 C92.2 C93.2 C94.2 C95.2 C96.2 C97.2 C98.2 C99.2 C100.2 C101.2 C102.2 C103.2 C104.2 C105.2 C106.2 C108.1 C109.2 C110.2 C111.2 C112.2 C113.2 C114.2 C115.2 C116.2 C117.2 C118.1 C119.1 C120.2 C121.1 C122.2 C123.2 C124.2 C125.1 C126.2 C127.2 C128.2 C129.2 C130.2 C131.2 C132.1 D1.2(GND) D2.1(ANODE) D3.1(ANODE) D4.2(CATHODE) D5.2(CATHODE) J2.1 J3.1 J4.1 J5.3 J6.3 J7.3 J8.3 J9.3 J10.A2 J10.A3 J10.A7 J10.A10 J10.A12 J10.A15 J10.A18 J10.A25 J10.A28 J10.B2 J10.B3 J10.B6 J10.B9 J10.B11 J10.B15 J10.B25 J10.B28 JP1.5 L5.1 P2.25(FG#25) P2.26(FG#26) P2.27(FG#27) P2.28(FG#28) P3.4(J4) P3.5(J5) P3.13(FG#13) P3.14(FG#14) P3.15(FG#15) P3.16(FG#16) P3.17(FG#17) P3.18(FG#18) P4.3(GND#3) P4.4(GND#4) P4.5(GND#5) P4.6(GND#6) R1.2 R2.2 R9.2 R12.2 R14.2 R15.2 R18.1 R26.1 R27.2 R30.1 R35.1 R38.1 R42.2 R44.1 R58.1 R60.1 R61.2 R63.1 R64.1 U1.2(GND) U4.2(GND) U5.5(GND#5) U5.6(GND#6) U5.7(GND#7) U5.8(GND#8) U6.7(GND) U7.4(GND) U7.7(TEST) U8.2(GND) U8.5(DIR) U9.5(GND#5) U9.6(GND#6) U9.7(GND#7) U9.8(GND#8) U10.55(GND#55) U10.63(GND#63) U10.65(GND#65) U11.6(XTALI) U11.7(XTALGND) U11.24(BIASGND) U11.29(AGND#29) U11.32(AGND#32) U11.40(OGND#40) U11.45(OGND#45) U11.54(DGND#54) U11.63(DGND#63) U12.3(GND) U13.25(GND) X1.3(GND) X2.2(GND) X3.2(GND)
VCC3P3: C53.1 C82.1 C84.1 C85.1 C87.1 C88.1 C89.1 J10.A21 J10.A22 P2.24(BRIGHT_LED+) R57.1 R82.2 R83.2 U4.7(VCCB) U5.1(EN) U5.2(VIN) U8.1(VREFA) U9.1(EN) U9.2(VIN)
VDD1P2: C86.1 C90.1 C91.1 C94.1 C95.1 C96.1 C97.1 C101.1 C102.1 C104.1 N3.2 N4.2 R8.1 U5.3(VOUT) U10.39(DVDD_1) U10.43(DVDD_2) U10.47(DVDD_3) U10.62(DVDD_4) U10.64(DVDD_5)
VDD2P5: C21.2 C55.2 C56.1 C57.2 C75.2 C76.2 C80.1 C81.1 C83.1 C92.1 C93.1 C98.1 C106.1 C107.1 C117.1 C120.1 C126.1 C127.1 C128.1 C129.1 L7.1 L8.1 L9.1 R5.1 R6.1 R7.2 R10.1 R11.2 R13.1 R16.1 R17.1 R20.2 R23.1 R29.1 R31.1 R36.1 T1.1(TCT1) T1.4(TCT2) T1.7(TCT3) T1.10(TCT4) U4.3(VCCA) U8.6(VREFB) U9.3(VOUT) U10.37(VDDO_1) U10.56(VDDO_2)
VDD5P0SB: F1.2 J10.A4 J10.A5 R81.1
VDD12P0: C16.1 C17.1 J10.A6 U2.3(VIN)
1PPS_OUT_CLK: D4.1(ANODE) J10.A1 P4.1(UP-IN)
88E1112_25M_REFCLK: J10.A26 R38.2 R39.1
88E1112_INT_L: J10.B26 U8.3(A1)
88E1112_RST_L: C22.1 J10.A24 U10.52(RESET)
5221_50M_RMII_REFCLK: J10.A13 U11.4(REF_CLK)
5221_ACTLED: R61.1 R62.2 U11.33(RCVLED#/ACTLED#) U12.2(INA)
5221_AVDD: C122.1 C123.1 C124.1 U11.22(BIASVDD) U11.27(AVDD#27) U11.28(AVDD#28)
5221_INT_L: J10.B12 U11.34(XMTLED#/INTR#/F)
5221_LNKACT: U6.5(I) U12.4(OUT)
5221_LNKACT_B: R78.1 U6.10(O)
5221_LNKACT_C: J10.A19 U6.8(O)
5221_RD_N: R65.1 T2.8(IN#) U11.25(RD-)
5221_RD_P: R68.1 T2.6(IN) U11.26(RD+)
5221_RST_L: J10.A11 U11.9(RESET#)
5221_SPDLED: R55.2 R59.2 R79.1 U12.1(INB)
5221_TD_N: R67.1 T2.3(TR#) U11.30(TD-)
5221_TD_P: R66.1 T2.1(TR) U11.31(TD+)
ANEN_5221: R54.1 U11.38(ANEN/TRST#)
BIAS3V3: C1.2 C4.2 C6.2 C12.2 C24.2 C56.2 C58.2 C72.2 C74.1 C77.1 C78.2 C79.1 C80.2 C107.2 C108.2 C118.2 C119.2 C121.2 C125.2 C132.2 J2.3 J3.3 J4.3 J5.1 J6.1 J7.1 J8.1 J9.1 J10.B21 J10.B22 L2.1 P2.18(TLEFT_LED+) P2.20(TRIGHT_LED+) R45.2 R54.2 R56.1 R59.1 R62.1 R70.2 R71.2 U6.14(VCC) U7.8(VCC) U11.1(OVDD#1) U11.3(REGDVDD) U11.8(OVDD/NC) U11.20(REGAVDD) U11.46(OVDD#46) U12.5(VCC) U13.26(VCC)
C1P: C60.2 U13.28(C1+)
C2N: C64.1 U13.2(C2-)
C2P: C64.2 U13.1(C2+)
CLK_25M_MNGPHY: R39.2 R41.2 R42.1 U10.36(XTAL1)
CLK_25M_OCXO: J1.2 J10.B10
CPU_PHY_SGMII_N: C28.1 J10.A30
CPU_PHY_SGMII_P: C29.1 J10.A29
FORCEOFF: R71.1 U13.22(FORCEOFF#)
FORCEON: R70.1 U13.23(FORCEON)
I2C_SCL_MG: J10.A23 U7.6(SCL)
I2C_SDA_MG: J10.B20 U7.5(SDA)
LED_ACT_MGMT1: P2.19(TRIGHT_LED-) R78.2
LED_ACT_MGMT_R: P2.23(BRIGHT_LED-) R77.2
LED_SPD_MGMT1_R: P2.17(TLEFT_LED-) R79.2
LED_STUS0_MGMT: R21.2 R25.2 R37.2 U6.1(I) U10.40(STATUS0)
LED_STUS0_MGMT_B: R77.1 U6.12(O)
LED_STUS0_MGMT_C: J10.A20 U6.4(O)
LED_STUS1_MGMT: P2.21(BLEFT_LED-) R22.2 R24.2 R28.2 R34.2 U10.38(STATUS1)
LP_5221: R60.2 U11.16(LOW_PWR)
MCT: C63.1 R86.2 R87.2 R88.2 R89.2
MCT1: R86.1 T1.24(MCT1)
MCT2: R87.1 T1.21(MCT2)
MCT3: R88.1 T1.18(MCT3)
MCT4: R89.1 T1.15(MCT4)
MDC_88E1112: J10.B23 R82.1 U4.1(B2)
MDC_5221: J10.B13 U11.42(MDC)
MDIO_88E1112: J10.B24 R83.1 U4.8(B1)
MDIO_5221: J10.B14 R45.1 U11.41(MDIO)
MGMT_INT#_2P5: R20.1 U8.4(B1) U10.61(INIT/INT)
MGT_TRD1_0_N: C38.1 R47.2 T1.11(TD4+) U10.19(/MDIN0)
MGT_TRD1_0_P: C37.1 R46.1 T1.12(TD4-) U10.18(MDIP0)
MGT_TRD1_0_TERM: C45.1 C46.1 R46.2 R47.1
MGT_TRD1_1_N: C40.1 R49.2 T1.8(TD3+) U10.22(/MDIN1)
MGT_TRD1_1_P: C39.1 R48.1 T1.9(TD3-) U10.21(MDIP1)
MGT_TRD1_1_TERM: C47.1 C48.1 R48.2 R49.1
MGT_TRD1_2_N: C42.1 R51.2 T1.5(TD2+) U10.28(/MDIN2)
MGT_TRD1_2_P: C41.1 R50.1 T1.6(TD2-) U10.27(MDIP2)
MGT_TRD1_2_TERM: C49.1 C50.1 R50.2 R51.1
MGT_TRD1_3_N: C44.1 R53.2 T1.2(TD1+) U10.31(/MDIN3)
MGT_TRD1_3_P: C43.1 R52.1 T1.3(TD1-) U10.30(MDIP3)
MGT_TRD1_3_TERM: C51.1 C52.1 R52.2 R53.1
MII_EN_5221: R63.2 U11.18(MII_EN)
MNG_PHY_CFG0: R17.2 R18.2 R21.1 R22.1 U10.48(CONFIG0)
MNG_PHY_CFG1: R23.2 R24.1 R25.1 R26.2 U10.46(CONFIG1)
MNG_PHY_CFG2: R28.1 R30.2 U10.45(CONFIG2)
MNG_PHY_CFG3: R31.2 R34.1 U10.44(CONFIG3)
MNG_PHY_CFG4: R35.2 U10.42(CONFIG4)
MNG_PHY_CFG5: R36.2 R37.1 U10.41(CONFIG5)
MNG_PHY_LOS_L: R10.2 R19.2 R80.1
MNG_PHY_LOS_R_L: R19.1 U10.59(/LOS)
MNG_PHY_MDC_2P5: R6.2 U4.4(A2) U10.57(MDC/SSCL)
MNG_PHY_MDIO_2P5: R5.2 U4.5(A1) U10.58(MDIO/SSDA)
MNG_PHY_NORMAL: R15.1 R16.2 U10.49(NORMAL)
MNG_PHY_POL_RST: R12.1 U10.51(POL_RST)
MNG_PHY_PWRDN: R13.2 R14.1 U10.50(PWRDN)
MNG_PHY_VDDA: C111.1 C112.1 C113.1 C114.1 C115.1 C116.1 L9.2 U10.20(VDDA_1) U10.23(VDDA_2) U10.24(VDDA_3) U10.29(VDDA_4) U10.33(VDDA_5)
MNG_PHY_VDDAH: C103.1 C109.1 C110.1 L8.2 U10.7(VDDAH_1) U10.14(VDDAH_2)
MNG_PHY_VDDAL: C99.1 C100.1 C105.1 L7.2 U10.6(VDDAL_1) U10.13(VDDAL_2)
MNG_SFP_RSET: R44.2 U10.17(RSET)
MNG_SGMII_C_N: C28.2 U10.8(/S_INN)
MNG_SGMII_C_P: C29.2 U10.9(S_INP)
MNGPHY_SDA: R11.1 U10.53(SDA)
MX0_A_0N: P2.6(T6) T2.14(T#)
MX0_A_0P: P2.3(T3) T2.16(T)
MX0_A_1N: P2.2(T2) T2.9(I#)
MX0_A_1P: P2.1(T1) T2.11(I)
MX_0+: P2.11(B3) T1.13(MX4-)
MX_0-: P2.14(B6) T1.14(MX4+)
MX_1+: P2.9(B1) T1.16(MX3-)
MX_1-: P2.10(B2) T1.17(MX3+)
MX_2+: P2.15(B7) T1.19(MX2-)
MX_2-: P2.16(B8) T1.20(MX2+)
MX_3+: P2.12(B4) T1.22(MX1-)
MX_3-: P2.13(B5) T1.23(MX1+)
PHY_CPU_SGMII_N: J10.B30 U10.1(/S_OUTN)
PHY_CPU_SGMII_P: J10.B29 U10.2(S_OUTP)
PHYAD_0: J5.2 U11.10(PHYAD0/FDX_LED#)
PHYAD_1: J6.2 U11.11(PHYAD1/COL_LED#)
PHYAD_2: J7.2 U11.12(PHYAD2/ACT_LED#)
PHYAD_3: J8.2 U11.13(PHYAD3/PAUSE)
PHYAD_4: J9.2 U11.14(PHYAD4/CK25)
RDAC: R64.2 U11.23(RDAC)
RJ45_RXD: D2.2(CATHODE) L4.2 P3.6(J6)
RJ45_TXD: D3.2(CATHODE) L6.2 P3.3(J3)
RMIICRSDV: J10.B17 R33.2
RMIICRSDV_R: R33.1 U11.49(RXDV)
RMIIRXD0: J10.B18 R40.2
RMIIRXD0_R: R40.1 U11.48(RXD0)
RMIIRXD1: J10.B19 R43.2
RMIIRXD1_R: R43.1 U11.47(RXD1)
RMIIRXER: J10.B16 R32.2
RMIIRXER_R: R32.1 U11.51(RXER)
RMIITXD0: J10.A16 U11.57(TXD0)
RMIITXD1: J10.A17 U11.58(TXD1)
RMIITXEN: J10.A14 U11.56(TXEN)
ROUT2: R72.2 U13.18(ROUT2)
RXD: R75.1 U13.5(RIN2)
TESTEN_5221: R58.2 U11.15(TESTEN)
TS_BITCLK_OUT: D5.1(ANODE) J10.B1 P4.2(IN-DOWN)
TXD: R76.1 U13.10(DOUT2)
UART1_3243_RXD: J10.A8 R72.1
UART1_3243_TXD: J10.A9 U13.13(DIN2)
USB1_DM: N2.2 N6.1 U14.1(1IN)
USB1_DM_C: D1.3(I/O2) N6.2 P3.10(D-) U14.2(1OUT)
USB1_DP: N1.2 N5.1 U14.4(2IN)
USB1_DP_C: D1.1(I/O1) N5.2 P3.11(D+) U14.3(2OUT)
USB1_DRVVBUS: J10.B8 R81.2 U1.4(EN)
USB1_GND_C: L5.2 P3.12(GND)
USB1_OC#: J10.B7 U1.3(FLG)
USB1_VBUS: L3.2 U1.1(VOUT)
USB1_VBUS_C: C67.1 C68.2 D1.5(VCC) L3.1 P3.9(VCC)
USB_CAB_DN: JP1.2 N2.3
USB_CAB_DP: JP1.3 N1.3
USB_MGT_DN: J10.B5 N2.1
USB_MGT_DP: J10.B4 N1.1
VN: C65.2 U13.3(V-)
VP: C61.2 R69.2 U13.27(V+)
N16967289: R56.2 U11.35(LNKLED#/MEDIA_C)
N16969721: C54.1 R66.2 R67.2
N16969742: C59.1 R65.2 R68.2
N16975167: C30.1 C32.1 C33.1 U11.2(DVDD#2)
N16979054: C25.1 C26.1 C27.1 U11.55(DVDD#55)
N16981835: TP3.1 U11.17(ENERGY_DET)
N16997753: R55.1 U11.36(SPDLED#/ADV_PAU)
N17348775: R7.1 U4.6(OE)
N17369682: C70.1 L4.1 R75.2
N17369686: C71.1 L6.1 R69.1 R76.2
N17369693: C60.1 U13.24(C1-)
N17377991: C15.1 JP1.1
N17393087: C130.1 C131.1 L2.2 T2.2(CT1) T2.7(CI1)
N17393095: C62.1 R84.2 R85.2
N17393120: R84.1 T2.15(CT2)
N17393125: R85.1 T2.10(CI2)
N17394746: P2.4(T4) P2.5(T5) R74.2
N17394754: P2.7(T7) P2.8(T8) R73.2
N17394762: C69.2 R73.1 R74.1
N17500188: U6.2(O) U6.3(I) U6.13(I)
N17503699: U6.6(O) U6.9(I) U6.11(I)
N17554281: R2.1 R3.2 U3.1(ADJ/GND)
N17554333: R1.1 R4.2 U2.1(ADJ/GND)
N17555126: J1.1 X1.4(OUT)
N17555132: J1.3 X2.3(CLK)
N17584781: J3.2 U7.2(A1)
N17584783: J2.2 U7.1(A0)
N17584789: J4.2 U7.3(A2)
N17714670: A4.2 A4.3 A4.4 A4.5 A4.6 A4.7 A4.8 A4.9 C66.1
N17714694: A2.2 A2.3 A2.4 A2.5 A2.6 A2.7 A2.8 A2.9 C3.1
N17714718: A3.2 A3.3 A3.4 A3.5 A3.6 A3.7 A3.8 A3.9 C73.1
N17714742: A1.2 A1.3 A1.4 A1.5 A1.6 A1.7 A1.8 A1.9 C5.1
N51850856: R27.1 R29.2 U9.4(ADJ)
N51850909: R8.2 R9.1 U5.4(ADJ)
N51852031: L1.1 R57.2
N51852050: R41.1 X3.3(CLK)
N51852054: C34.1 C35.1 C36.1 L1.2 X3.1(OE) X3.4(VCC)
N51852604: C23.2 N3.1 U10.3(S_VTT)
N51852612: C31.2 N4.1 U10.12(F_VTT)
N57500449: P2.22(BLEFT_LED+) R80.2
N172653170: TP2.1 U11.61(COL)
N172654950: TP1.1 U11.62(CRS/CRS_DV)

Pads without a net: B1 1 2; B2 1 2; B3 1 2; D1 4 6; J10 A27 B27; JP1 4; P3 1 2 7 8; T2 4 5 12 13; U10 4 5 10 11 15 16 25 26 32 34 35 54 60; U11 5 19 21 37 39 43 44 50 52 53 59 60 64; U13 4 6 7 8 9 11 12 14 15 16 17 19 20 21; X1 1 2 5; X2 1

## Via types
v1: diameter 0.508, hole 0.254, TOP to BOTTOM, 795 vias
v2: diameter 0.635, hole 0.318, TOP to BOTTOM, 31 vias
v3: diameter 0.635, hole 0.381, TOP to BOTTOM, 76 vias
v4: diameter 0.762, hole 0.508, TOP to BOTTOM, 76 vias
v5: diameter 0.635, hole 0.254, TOP to BOTTOM, 6 vias
v6: diameter 0.762, hole 0.381, TOP to BOTTOM, 2 vias
v7: diameter 0.889, hole 0.508, TOP to BOTTOM, 2 vias

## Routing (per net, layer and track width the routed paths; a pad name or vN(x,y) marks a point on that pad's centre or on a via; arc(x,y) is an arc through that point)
3.3V_OCXO: length 31.7
  TOP w0.305: C7.1 45.55,125.04 ; C7.1 46.14,125.66 ; C7.1 46.14,124.61 ; C8.1 46.14,123.33 ; C8.1 45.49,123.9 ; C8.1 46.14,124.42
  TOP w0.508: 45.48,119.3 C11.1 ; C11.1 45.91,119.95 ; C11.1 45.91,118.66 ; 46.04,121.96 C9.1 ; C9.1 45.61,122.61 ; C9.1 46.04,123.25 ; C10.1 45.9,121.79 ; C10.1 45.9,120.12 ; C10.1 45.36,120.95 ; 42.21,101.65 U3.2 ; U3.2 41.27,102.34 ; U3.2 42.21,103.02 ; U3.2 43.16,102.34 ; X1.6 41.89,134.53 ; X1.6 41.07,135.92 ; X1.6 41.07,133.15 ; X1.6 40.26,134.53 ; 48.01,102.34 U3.4 ; U3.4 49.07,104.42 ; U3.4 49.07,100.25 ; U3.4 50.14,102.34 ; 50.46,104.86 C14.1 ; C14.1 50.46,106.54 ; C14.1 49.93,105.7 ; 50.64,107.38 C13.1 ; C13.1 51.08,106.73 ; C13.1 51.08,108.03 ; R3.1 51.08,104.68 ; R3.1 50.64,104.03 ; R3.1 51.08,103.38 ; 40.91,126.24 X2.4 ; X2.4 41.91,125.24 ; X2.4 42.92,126.24
  vias: v2(47.09,106.96)
5V_IN: length 5.7
  TOP w0.254: F1.1 6.83,172.85 v2(7.42,173.43)
  TOP w0.508: U1.5 6.95,168.11 C2.1 6.95,171.57 F1.1
7V_OCXO: length 20.5
  TOP w0.508: U2.4 34.24,105.28 ; U2.4 33.17,103.2 ; U2.4 34.24,101.12 ; U2.4 35.31,103.2 ; 26.44,103.2 U2.2 ; U2.2 27.37,103.19 R4.1 ; U2.2 27.38,102.51 ; U2.2 28.32,103.2 ; 39.33,99.73 C20.1 ; C20.1 40.63,99.73 ; C20.1 39.98,100.17 ; C18.1 36.55,100.53 ; C18.1 35.71,100 ; C18.1 37.39,100 ; 42.21,99.36 U3.3 ; U3.3 41.27,100.05 ; U3.3 42.21,100.74 ; U3.3 43.16,100.05 ; C19.1 38.33,100.53 ; C19.1 39.17,100 ; C19.1 37.49,100
  vias: v2(36.91,103.4)
GND: length 613.2
  TOP w0.254: U11.24 16.01,67.95 v3(16.21,68.15) ; v3(8.97,74.03) 9.11,73.89 U11.6 ; U11.7 9.46,73.39 9.21,73.14 v3(9.19,73.14) ; v1(31.97,83.86) 31.64,83.86 31.38,84.12 U10.63 ; v1(45.49,92.89) 45.23,93.15 U4.2 ; v3(20.83,74.57) 21.15,74.89 U11.45 ; U11.40 v3(20.86,72.39) ; U11.63 v3(13.01,77.27) ; v1(35.44,83.86) 35.38,83.91 U10.55 ; U11.32 v3(20.11,68.06) ; U11.54 v3(17.51,77.19) ; v3(18.3,68.44) 18.51,68.24 U11.29
  TOP w0.305: J5.3 7.73,74.05 v1(7.8,74.12) ; C71.2 v1(29.29,29.97) ; v1(45.38,78.96) 45.2,78.78 R38.1 ; C12.1 v1(6.82,110.97) ; R9.2 v1(34.62,92.59) ; C70.2 17.99,29.85 v1(18.24,30.1) ; C6.1 v1(6.15,144.96) ; C1.1 9.5,174.68 v1(9.32,174.85) ; C53.2 v3(47.32,68.02) ; v1(29.67,62.15) 29.89,62.37 C57.1 ; C58.1 v1(7.02,63.47) ; C4.1 v1(21.36,161.43) ; C21.1 50.95,91.41 v1(50.85,91.52) ; R27.2 v1(47.46,81.59) ; C72.1 v1(12.69,29.31) ; C24.1 v1(6.21,81.36) ; C55.1 v1(52.55,63.68)
  TOP w0.356: C17.2 v3(23.77,99.72) ; C65.1 v1(7.87,45.09) ; R63.1 v1(13.11,63.2) ; v1(26.92,71.53) 26.94,71.51 C37.2 ; C54.2 v1(21.35,65.35) ; C22.2 v1(36.2,89.03) ; C8.2 v3(47.65,123.9) ; C48.2 34.54,68.78 v1(34.65,68.68) ; v1(44.27,82.45) 44.25,82.43 R30.1 ; C33.2 6.19,75.89 v1(6.15,75.84) ; v1(38.73,91.91) 38.73,91.93 38.57,92.09 U8.5 ; v1(6.1,68.07) R58.1 ; C43.2 v1(41.02,70.87) ; C7.2 v3(47.65,125.04) ; v3(47.74,74.6) 47.74,74.61 C34.2 ; C31.1 26.98,77.54 v1(26.27,78.24) ; C50.2 v1(38.99,68.78) ; v1(45.12,83.72) 45.06,83.78 R26.1 ; R35.1 43.13,79.78 v1(43.15,79.81) ; v1(35.46,70.87) 35.56,70.97 C40.2 ; R44.1 28.21,73.48 v1(28.28,73.4) ; v3(5.87,103.53) 5.88,103.52 C15.2 ; v1(8.51,54.48) 8.27,54.73 U13.25 ; C74.2 v1(50.78,27.88) ; C47.2 v1(33.15,68.78) ; C42.2 v1(40.01,70.79) ; v1(14,63.53) 14.26,63.79 R64.1 ; R12.2 v1(37.21,89.05) ; C49.2 v1(37.59,68.81) ; C46.2 v1(30.1,68.81) ; v1(36.67,91.89) 36.48,92.09 U8.2 ; R61.2 v1(22.42,64.81) ; R14.2 v1(39.24,89.08) ; C32.2 6.1,76.78 v1(6.1,76.78) ; C44.2 44.45,70.79 v1(44.48,70.76) ; C45.2 v1(28.7,68.83) ; C41.2 v1(36.58,70.59) ; v3(47.74,73.57) 47.97,73.57 47.98,73.56 C35.2 ; C30.2 v1(6.12,77.67) ; C68.1 v3(11.96,31.01) ; C38.2 v1(31.11,70.76) ; C23.1 26.84,82.27 v1(26.3,81.72) ; C61.1 v1(6.86,59.44) ; R60.1 v1(6.17,67.03) ; R15.2 v1(40.26,89) ; C25.2 v1(17.16,82.64) ; C27.2 v1(19.2,82.63) ; C59.2 v1(15.11,61.87) ; v1(43.21,89.1) 43.36,88.95 R18.1 ; C52.2 v1(43.43,68.83) ; C26.2 v1(18.18,82.61) ; C39.2 v1(32.13,70.79) ; C51.2 v1(42.04,68.83)
  TOP w0.381: J6.3 v1(8.46,72.31) ; J9.3 v1(8.48,69.21) ; J8.3 8.48,70.24 v1(8.48,70.23) ; J7.3 v1(8.55,71.28)
  TOP w0.508: 36.39,83.74 34.63,81.99 ; 34.63,81.99 34.63,83.65 ; 34.63,81.99 34.63,81.89 ; v1(25.4,91.52) 25.43,91.5 U6.7 ; 9.98,90.02 U7.4 ; U7.4 11.25,90.02 ; U7.4 10.62,91.13 10.29,91.47 9.09,91.47 v1(9.07,91.49) ; U7.4 10.62,89.14 ; 30.45,95.38 U5.6 ; U5.6 v1(30.45,97.38) ; U5.6 30.96,96.25 ; U5.6 29.95,96.25 ; 7.03,76.32 C33.2 7.03,75.46 ; U9.6 52.87,86.39 ; U9.6 52,85.88 ; U9.6 52,86.9 ; U9.6 50.93,86.39 v1(50.91,86.41) ; 34.63,81.89 32.78,83.75 ; 34.63,81.89 U10.65 ; U5.7 29.69,96.25 ; U5.7 28.68,96.25 ; U5.7 29.18,95.38 ; U5.7 v1(29.18,97.33) ; 9.04,1.66 P4.4 ; P4.4 11.81,1.66 ; P4.4 10.42,3.05 ; U5.8 v1(27.79,97.36) ; U5.8 28.42,96.25 ; U5.8 27.79,95.38 ; 34.8,80.29 37.76,77.33 ; 34.8,80.29 35.15,80.29 ; 34.8,80.29 U10.65 ; P3.13 15.15,6.29 ; P3.13 15.15,3.13 ; P3.13 13.57,4.71 ; P3.13 16.73,4.71 ; P3.16 33.85,18.97 ; P3.16 33.85,15.81 ; P3.16 32.27,17.39 ; 47.72,71.22 C36.2 ; C36.2 47.19,72.06 ; C36.2 47.72,72.9 ; 37.87,11.03 P2.28 37.87,8.01 ; X1.3 36.81,142.79 ; X1.3 35.18,142.79 ; X1.3 35.99,144.17 ; U9.8 52,89.69 ; U9.8 52.87,89.06 ; U9.8 50.89,89.06 v1(50.89,89.05) ; U9.8 52,88.42 ; P4.5 3.57,11.95 ; P4.5 3.57,9.18 ; P4.5 2.19,10.56 ; P4.5 4.96,10.56 ; 2.19,1.66 P4.6 ; P4.6 4.96,1.66 ; P4.6 3.57,3.05 ; 46.2,78.26 X3.2 ; X3.2 48.08,78.26 ; X3.2 47.14,77.44 ; 36.62,76.83 34.63,78.82 34.63,78.97 ; P3.5 23.87,20.91 ; P3.5 24.74,20.03 ; P3.5 23.87,19.15 ; P3.5 22.99,20.03 ; D1.2 v4(22.96,27.18) ; v1(50.89,85) 50.91,84.99 U9.5 ; 39.33,98.44 C20.2 ; C20.2 40.63,98.44 ; C20.2 39.98,97.6 v4(39.98,97.6) ; P3.15 16.73,17.39 ; P3.15 15.15,15.81 ; P3.15 15.15,18.97 ; U9.5 52,85.63 ; U9.5 52,84.36 ; U9.5 52.87,84.99 ; 11.81,10.56 P4.3 10.42,9.18 ; C2.2 8.68,169.79 ; C2.2 8.25,168.83 v1(8.02,168.61) ; C2.2 8.25,170.44 ; 47.73,121.79 C10.2 47.73,120.12 ; U5.5 32.49,96.25 ; U5.5 31.85,97.33 v1(31.83,97.36) ; U5.5 31.22,96.25 ; U5.5 31.85,95.38 ; U10.65 34.6,80.29 ; U10.65 34.63,78.97 ; 34.6,80.29 34,80.29 ; 34.6,80.29 34.6,76.85 ; 17.6,81.84 C25.2 16.73,81.84 ; v1(7.96,166.7) 7.95,166.69 U1.2 ; U6.7 24.79,90.34 ; U6.7 25.43,89.46 ; U6.7 26.06,90.34 ; 52,87.15 U9.7 ; U9.7 52.87,87.66 ; U9.7 52,88.17 ; U9.7 50.92,87.66 v1(50.91,87.67) ; 54.12,19.41 P2.25 54.12,16.39 ; 54.12,8.01 P2.27 ; P2.27 54.12,11.03 ; P2.27 52.8,9.52 ; C16.2 23.04,101.02 v4(22.99,100.97) ; C16.2 24.04,100.37 ; C16.2 24.04,101.66 ; 33.61,80.29 34,80.29 ; 33.61,80.29 31.63,80.29 ; 33.61,80.29 31.63,78.31 ; 34,80.29 31.78,82.51 ; 35.15,80.29 37.69,82.83 ; 35.15,80.29 37.48,80.29 ; v4(54.62,108.07) 54.57,108.07 53.88,107.38 C13.2 ; R2.2 v4(40.11,106.86) ; R2.2 39.46,105.98 ; R2.2 40.75,105.98 ; R42.2 41.4,75.29 v1(40.61,74.5) ; D3.1 30.74,27.7 ; D3.1 30.18,28.39 ; D3.1 30.18,27.01 ; 7.03,76.35 C32.2 7.03,77.21 ; 25.14,16.61 P3.4 ; P3.4 26.01,17.49 ; P3.4 24.26,17.49 ; P3.4 25.14,18.37 ; 18.88,27.19 D2.1 18.33,27.87 ; v1(8.61,84.2) 9.17,84.76 J4.1 ; U7.7 7.95,96.61 ; U7.7 7.95,94.44 v1(7.87,94.36) ; U7.7 8.46,95.74 ; U7.7 7.44,95.74 ; C9.2 v3(48.34,122.61) ; C9.2 47.33,123.25 ; C9.2 47.33,121.96 ; J4.1 9.6,85.55 ; J4.1 8.74,85.55 ; R1.2 25.79,106.77 ; R1.2 25.15,107.2 ; R1.2 v4(24.14,106.77) ; C11.2 v3(48.08,119.3) ; C11.2 47.21,118.66 ; C11.2 47.21,119.95 ; 33.2,26.28 L5.1 32.57,26.87 ; 17.93,5.76 P3.17 ; P3.17 19.51,7.34 ; P3.17 16.35,7.34 ; P3.17 17.93,8.92 ; 3.12,110.74 3.94,110.74 ; 3.94,110.74 4.75,110.74 ; 3.94,110.74 3.94,109.93 ; 3.94,110.74 3.94,111.56 ; C67.2 24.31,35.31 ; C67.2 22.1,36.12 ; C67.2 19.89,35.31 ; J3.1 v1(7.11,85.55) ; J3.1 8.33,85.55 ; J3.1 7.9,85.11 ; 7.03,78.1 C30.2 7.03,77.24 ; 33.85,3.13 P3.14 ; P3.14 33.85,6.29 ; P3.14 32.27,4.71 ; P3.14 35.43,4.71 ; C13.2 52.37,106.73 ; C13.2 52.37,108.03 ; 6.38,85.11 J2.1 ; J2.1 6.81,85.55 ; J2.1 v1(5.51,85.55) ; 37.87,16.39 P2.26 37.87,19.41 ; 7.79,16.74 D4.2 8.35,16.05 ; P3.18 31.07,8.92 ; P3.18 31.07,5.76 ; P3.18 29.49,7.34 ; P3.18 32.65,7.34 ; 39.17,98.17 C19.2 37.49,98.17 ; 20.54,66.83 U11.32 20.11,65.95 ; 18.61,81.84 C26.2 17.75,81.84 ; 37.39,98.17 C18.2 35.71,98.17 ; 20.92,64.65 C54.2 21.79,64.65 ; 34.63,78.97 32.47,76.81 ; U12.3 v1(24.45,65.45)
  TOP w0.635: C10.2 v4(48.59,120.95) ; C18.2 36.55,97.3 v4(36.53,97.28) ; v4(53.57,105.09) 52.96,105.7 C14.2 ; C36.2 47.05,71.39 v4(47.05,70.76) ; v4(38.33,97.29) 38.33,97.29 C19.2
  TOP w0.762: C3.2 v4(53.25,167.26) ; C3.2 v4(52.12,168.35) ; C3.2 v4(51.14,167.26) ; C66.2 v4(52.6,40.89) ; C66.2 v4(51.54,39.87) ; C66.2 v4(51.54,41.95) ; 22.1,35.1 22.1,35.15 ; 22.1,35.1 v4(20.95,33.96) ; 22.1,35.1 v4(22.1,33.76) ; 22.1,35.15 C67.2 ; 22.1,35.15 v4(23.22,34.04) ; D5.2 v4(11.14,17.86) ; v4(37.01,131.34) 35.91,130.25 X2.2 35.9,130.24 v4(34.87,131.27) ; C5.2 v3(5.79,151.56) ; C5.2 4.8,152.7 v4(4.79,152.7) ; C5.2 v4(6.88,152.7) ; v4(17.96,57.28) 17.65,56.97 C62.2 ; v4(33.18,27.82) 33.18,27.7 33.2,27.69 L5.1 ; D4.2 v4(8.35,17.83) ; C62.2 v4(15.85,55.47) ; C62.2 v4(19.28,55.47) ; C63.2 v4(51.31,55.83) ; C63.2 v4(52.86,53.82) ; C63.2 v4(49.68,53.82) ; C73.2 v4(6.83,27.71) ; C73.2 v4(8.98,27.71) ; C73.2 v4(7.95,26.44) ; v4(36.75,140.82) 35.99,141.58 ; 35.99,141.58 35.99,141.2 v4(35.48,140.69) ; 35.99,141.58 X1.3 ; C69.1 v4(32.36,30.48) ; C69.1 v4(34.11,29.08) ; C69.1 v4(34.11,31.93) ; D3.1 v4(29.27,27.7) ; D2.1 v4(18.88,29.04)
  TOP w1.016: X3.2 47.14,79.3 v1(47.19,79.35)
  L2_GND w0.508: P2.28 37.87,11.03 ; P2.28 37.87,8.01 ; P2.28 36.55,9.52 ; 17.93,5.76 P3.17 ; P3.17 17.93,8.92 ; P3.17 16.35,7.34 ; P3.17 19.51,7.34 ; 2.19,10.56 P4.5 ; P4.5 3.57,11.95 ; P4.5 3.57,9.18 ; P4.5 4.96,10.56 ; 37.87,16.39 P2.26 ; P2.26 36.55,17.9 ; P2.26 37.87,19.41 ; 2.19,1.66 P4.6 ; P4.6 3.57,3.05 ; P4.6 4.96,1.66 ; 15.15,15.81 P3.15 ; P3.15 16.73,17.39 ; P3.15 13.57,17.39 ; P3.15 15.15,18.97 ; P3.14 35.43,4.71 ; P3.14 33.85,6.29 ; P3.14 32.27,4.71 ; P3.14 33.85,3.13 ; U10.65 34.63,80.85 ; U10.65 35.19,80.29 ; U10.65 34.08,80.29 ; U10.65 34.63,79.74 ; 3.94,110.74 4.75,110.74 ; 3.94,110.74 3.94,109.93 ; 3.94,110.74 3.94,111.56 ; 3.94,110.74 3.12,110.74 ; 33.85,15.81 P3.16 ; P3.16 35.43,17.39 ; P3.16 33.85,18.97 ; P3.16 32.27,17.39 ; P2.25 55.45,17.9 ; P2.25 54.12,19.41 ; P2.25 54.12,16.39 ; P4.3 10.42,11.95 ; P4.3 9.04,10.56 ; P4.3 11.81,10.56 ; P4.3 10.42,9.18 ; 24.26,17.49 P3.4 ; P3.4 25.14,16.61 ; P3.4 26.01,17.49 ; P3.4 25.14,18.37 ; 54.12,8.01 P2.27 ; P2.27 55.45,9.52 ; P2.27 52.8,9.52 ; P2.27 54.12,11.03 ; P4.4 11.81,1.66 ; P4.4 9.04,1.66 ; P4.4 10.42,3.05 ; 22.99,20.03 P3.5 ; P3.5 24.74,20.03 ; P3.5 23.87,19.15 ; P3.5 23.87,20.91 ; 31.07,5.76 P3.18 ; P3.18 31.07,8.92 ; P3.18 29.49,7.34 ; P3.18 32.65,7.34 ; 15.15,3.13 P3.13 ; P3.13 16.73,4.71 ; P3.13 13.57,4.71 ; P3.13 15.15,6.29
  BOTTOM w0.305: C81.2 45.35,93.03 v1(45.49,92.89) ; C91.2 40.29,86.48 v3(40.57,86.75) ; C102.2 30.82,79.76 v1(31.22,79.36) ; v1(26.7,98.41) 26.72,98.39 C76.1 ; C97.2 29.38,83.78 29.16,84 v1(29.16,84.7) ; C82.2 42.19,92.41 v1(42.24,92.46) ; C75.1 v1(51.96,98.12) ; C111.2 39.61,75.83 v1(40.18,75.26) ; v3(9.19,73.14) 9.39,72.94 C121.1
  BOTTOM w0.356: v3(30.24,75.15) 30.42,75.15 30.95,75.69 C116.2 ; C115.2 v1(33.16,76.72) ; C114.2 v1(35.55,76.72) ; C122.2 v3(17.28,68.39) ; C93.2 35.55,83.96 v1(35.44,83.86) ; v3(24.72,82.94) 24.85,83.07 C98.2 ; v1(7.87,94.36) 7.61,94.63 C78.1 ; v1(29.18,79.27) 29.32,79.41 C103.2 ; C127.2 v1(40.34,61.57) ; C113.2 37.71,76.52 v1(37.47,76.76) ; v1(37.95,79.98) 38.34,80.38 C104.2 ; C84.2 36.51,92.05 v1(36.67,91.89) ; v1(39.12,85.29) 39.24,85.17 C96.2 ; C129.2 v1(48.08,61.52) ; v3(14.83,68.73) 15.07,68.5 C123.2 ; C77.2 18.4,97.68 v1(18.39,97.69) ; C109.2 27.94,75.44 v4(28.27,75.11) ; v1(38.73,91.91) 38.73,91.93 38.6,92.06 C83.2 ; v1(29.33,85.94) 29.86,85.41 C95.2 ; v1(38,82.75) 38.47,82.28 C101.2 ; C128.2 v1(36.53,61.62) ; C94.2 31.51,84.33 v1(31.97,83.86) ; C108.1 9.74,76.62 v3(9.27,77.09) ; C79.2 v1(18.4,94.76) ; C124.2 v3(18.3,68.44) ; v3(9.14,75.36) 9.22,75.43 C118.1 ; C132.1 8.24,54.75 v1(8.51,54.48) ; C110.2 29.53,76.09 29.2,75.76 v1(28.91,75.76) ; v1(27.84,84.88) 28.24,84.48 C99.2 ; v1(38.13,77.37) 38.49,77.74 C106.2 ; C131.2 v1(22.16,56.4) ; C125.1 v3(13.95,68.12) ; C126.2 v1(44.12,61.62) ; C117.2 44.93,75.86 45.29,75.5 v3(45.29,75.23) ; v1(31.07,82.54) C100.2 ; v4(27.37,73.55) 27.56,73.73 C120.2 ; C119.1 21.02,74.76 v3(20.83,74.57) ; C130.2 v1(28.48,56.32)
  BOTTOM w0.508: P4.5 4.96,10.56 ; P4.5 3.57,9.18 ; P4.5 2.19,10.56 ; P4.5 3.57,11.95 ; P4.4 10.42,3.05 ; P4.4 9.04,1.66 ; P4.4 11.81,1.66 ; P3.15 16.73,17.39 ; P3.15 15.15,15.81 ; P3.15 13.57,17.39 ; P3.15 15.15,18.97 ; P4.6 4.96,1.66 ; P4.6 2.19,1.66 ; P4.6 3.57,3.05 ; 32.33,89.76 C86.2 ; C86.2 32.33,91.75 v3(32.26,91.82) ; C86.2 32.86,90.6 ; P2.28 37.87,11.03 ; P2.28 36.55,9.52 ; P2.28 37.87,8.01 ; 3.94,110.74 4.75,110.74 ; 3.94,110.74 3.94,111.56 ; 3.94,110.74 3.12,110.74 ; 3.94,110.74 3.94,109.93 ; v1(18.47,170.64) 18.2,170.9 J10.B2 ; v4(41.66,74.22) C112.2 ; C112.2 42.3,75.17 ; C112.2 41.01,75.17 ; 34.63,79.74 U10.65 ; U10.65 35.19,80.29 ; U10.65 34.63,80.85 ; U10.65 34.08,80.29 ; P4.3 10.42,11.95 ; P4.3 11.81,10.56 ; P4.3 10.42,9.18 ; P4.3 9.04,10.56 ; P3.17 17.93,8.92 ; P3.17 19.51,7.34 ; P3.17 17.93,5.76 ; P3.17 16.35,7.34 ; C105.2 31.33,77.07 v1(31.3,77.05) ; C105.2 31.33,78.78 ; C105.2 31.76,78.13 ; 32.27,4.71 P3.14 ; P3.14 33.85,6.29 ; P3.14 35.43,4.71 ; P3.14 33.85,3.13 ; 33.85,15.81 P3.16 ; P3.16 35.43,17.39 ; P3.16 33.85,18.97 ; P3.16 32.27,17.39 ; J10.B9 23.8,173.94 v1(23.77,173.96) ; 54.12,16.39 P2.25 54.12,19.41 ; 15.5,67.55 C123.2 14.64,67.55 ; 44.21,89.13 C88.2 44.74,88.29 ; P3.13 16.73,4.71 ; P3.13 13.57,4.71 ; P3.13 15.15,3.13 ; P3.13 15.15,6.29 ; J10.A12 26.2,169.31 v1(25.88,169.63) ; v1(18.41,169.49) 18.2,169.28 J10.A2 ; 23.87,19.15 P3.5 ; P3.5 23.87,20.91 ; P3.5 22.99,20.03 ; J10.A25 36.6,169.39 v1(36.75,169.54) ; 16.85,67.55 C122.2 17.72,67.55 ; v1(30.93,169.41) 31,169.35 J10.A18 ; v3(29.06,88.7) 29.21,88.85 C87.2 ; C89.2 44.89,87.53 44.6,87.82 v4(44.58,87.82) ; 18.73,67.54 C124.2 17.87,67.54 ; 25.97,86.46 C90.2 ; C90.2 26.4,87.67 26.02,88.06 v1(25.86,88.06) ; C90.2 26.4,85.81 ; J10.B6 21.4,173.8 21.41,173.81 v1(21.41,174.1) ; v1(19.3,169.44) 19,169.14 J10.A3 ; 29.49,7.34 P3.18 ; P3.18 31.07,5.76 ; P3.18 31.07,8.92 ; P3.18 32.65,7.34 ; J10.B28 v1(39,170.84) ; P2.26 39.2,17.9 ; P2.26 37.87,19.41 ; P2.26 36.55,17.9 ; P2.26 37.87,16.39 ; 54.12,8.01 P2.27 ; P2.27 54.12,11.03 ; P2.27 52.8,9.52 ; J10.A15 28.6,169.29 28.6,169.29 v1(28.6,169.47) ; J10.B25 v1(36.6,170.84) ; v1(24.5,169.46) 24.6,169.36 J10.A10 ; J10.B15 28.6,173.63 v1(28.19,174.04) ; C92.2 v3(47.57,84.38) ; v1(19.3,170.64) 19,170.94 J10.B3 ; J10.A7 v1(22.2,169.49) ; 24.26,17.49 P3.4 25.14,16.61 ; 28.4,92.19 C85.2 27.56,92.72 ; J10.B11 v1(25.4,173.94) ; J10.A28 v1(39,169.52)
  BOTTOM w0.635: C88.2 v4(44.74,90.52) ; C85.2 v4(26.28,92.19)
  vias: v1(1.4,178.61) v1(1.4,176.3) v1(1.4,173.76) v1(1.4,171.22) v1(1.4,168.68) v1(1.4,166.14) v1(1.4,163.6) v1(1.4,161.06) v1(1.4,158.52) v1(1.4,155.98) v1(1.4,153.44) v1(1.4,150.9) v1(1.4,148.36) v1(1.4,145.82) v1(1.4,143.28) v1(1.4,140.74) v1(1.4,138.2) v1(1.4,135.66) v1(1.4,133.12) v1(1.4,130.58) v1(1.4,128.04) v1(1.4,125.5) v1(1.4,122.96) v1(1.4,120.42) v1(1.4,117.88) v1(1.4,115.34) v1(1.4,112.8) v1(1.4,110.26) v1(1.4,107.72) v1(1.4,105.18) v1(1.4,102.64) v1(1.4,100.1) v1(1.4,97.56) v1(1.4,95.02) v1(1.4,92.48) v1(1.4,89.94) v1(1.4,87.4) v1(1.4,84.86) v1(1.4,82.32) v1(1.4,79.78) v1(1.4,77.24) v1(1.4,74.7) v1(1.4,72.16) v1(1.4,69.62) v1(1.4,67.08) v1(1.4,64.54) v1(1.4,62) v1(1.4,59.46) v1(1.4,56.92) v1(1.4,54.38) v1(1.4,51.84) v1(1.4,49.3) v1(1.4,46.76) v1(1.4,44.22) v1(1.4,41.68) v1(1.4,39.14) v1(1.4,36.6) v1(1.4,34.06) v1(1.4,31.52) v1(1.4,28.98) v1(1.4,26.44) v1(1.4,23.9) v1(1.4,21.36) v1(1.4,18.82) v1(1.4,16.28) v1(1.4,13.74) v1(1.4,11.2) v1(1.4,8.66) v1(1.4,6.12) v1(1.4,3.58) v1(1.37,1.35) v1(3,138.1) v1(3.12,4.27) v1(3.3,23.8) v1(3.45,147.12) v1(3.78,165.18) v1(3.76,17.3) v1(3.94,178.61) v1(4.09,42.62) v1(4.32,49.91) v1(4.42,88.62) v1(4.42,75.23) v1(4.52,84.51) v1(4.47,79.98) v1(4.52,61.8) v1(4.52,56.24) v1(4.8,94.46) v1(5,99.49) v1(5.54,29.39) v1(5.64,118.54) v1(6.12,141.22) v1(6.48,178.61) v1(6.53,136.91) v1(6.45,1.35) v1(6.83,149.66) v1(7.01,108.92) v1(7.29,92.35) v1(7.39,52.73) v1(7.59,114.3) v1(7.72,176.63) v1(8.26,98.35) v1(8.31,61.37) v1(8.28,1.8) v1(8.36,93.24) v1(9.02,178.61) v1(9.8,163.88) v1(9.86,46) v1(10.08,80.34) v1(10.13,42.14) v1(10.39,39.73) v1(10.46,60.58) v1(10.74,77.88) v1(10.72,25.15) v1(10.95,5.94) v1(11.4,57.61) v1(11.51,53.87) v1(11.56,178.61) v1(11.56,50.65) v1(12.22,176.96) v1(12.37,81.58) v1(12.83,60.43) v1(12.75,38.46) v1(12.93,22.71) v1(13,68.38) v1(13.23,74.24) v1(13.31,32.49) v1(13.44,11.71) v1(13.67,7.95) v1(14.1,178.61) v1(14.07,1.35) v1(14.4,60.38) v1(15.62,76.43) v1(15.6,70.69) v1(16.26,73.03) v1(16.64,178.61) v1(16.61,1.35) v1(17.32,46.02) v1(17.32,38.51) v1(17.57,176.62) v1(18.06,75.29) v1(18.8,44.65) v1(19.18,178.61) v1(19.2,70.82) v1(19.15,1.35) v1(20.57,3.28) v1(20.88,55.07) v1(21.11,176.59) v1(21.36,150.11) v1(21.44,107.57) v1(21.72,178.61) v1(21.72,133.99) v1(21.72,123.24) v1(21.67,22.89) v1(21.69,1.35) v1(21.77,139.7) v1(22.2,112.83) v1(22.94,114.1) v1(22.89,104.8) v1(22.86,53.49) v1(23.06,102.29) v1(23.44,55.52) v1(23.73,163.07) v1(23.7,146.15) v1(23.7,143.61) v1(23.7,141.07) v1(23.7,138.53) v1(23.7,135.99) v1(23.7,133.45) v1(23.7,130.91) v1(23.7,128.37) v1(23.67,36.98) v1(24.11,153.64) v1(24.13,124.74) v1(24.08,120.02) v1(24.16,5.79) v1(24.23,1.35) v1(24.26,178.61) v1(24.26,39.45) v1(24.43,116.66) v1(24.71,108.48) v1(24.99,43.43) v1(25.6,59.72) v1(26.39,127.36) v1(26.39,124.82) v1(26.39,122.28) v1(26.39,119.74) v1(26.39,117.2) v1(26.47,148.44) v1(26.47,146.15) v1(26.47,143.61) v1(26.47,141.07) v1(26.47,138.53) v1(26.47,135.99) v1(26.47,133.45) v1(26.47,131.42) v1(26.47,114.91) v1(26.8,178.61) v1(26.77,1.35) v1(26.88,152.93) v1(27.1,23.29) v1(27.51,55.3) v1(27.91,128.73) v1(28.04,131.19) v1(27.99,107.57) v1(28.24,148.44) v1(28.91,3.91) v1(29.01,114.91) v1(29.34,178.61) v1(29.31,1.35) v1(29.64,100.33) v1(29.67,111.2) v1(29.9,131.17) v1(29.92,53.37) v1(29.97,128.7) v1(30.1,159.82) v1(30.73,61.04) v1(30.78,148.44) v1(30.84,22.96) v1(31.45,69.49) v1(31.55,114.91) v1(31.65,150.11) v1(31.7,128.75) v1(31.78,57.86) v1(31.88,178.61) v1(31.85,131.17) v1(31.85,1.35) v1(32.23,37.49) v1(32.44,64.34) v1(32.77,82.55) v1(32.77,81.41) v1(32.77,80.26) v1(32.77,79.12) v1(32.77,77.98) v1(32.89,34.24) v1(33.17,13.92) v1(33.27,152.3) v1(33.32,148.44) v1(33.4,107.54) v1(33.58,52.53) v1(33.58,9.73) v1(33.66,82.55) v1(33.66,81.41) v1(33.66,80.26) v1(33.66,79.12) v1(33.66,77.98) v1(33.78,177.11) v1(33.88,37.03) v1(33.99,160.32) v1(34.09,114.91) v1(34.06,58.04) v1(34.26,96.04) v1(34.42,178.61) v1(34.39,1.35) v1(34.7,98.02) v1(34.67,82.55) v1(34.67,81.41) v1(34.67,79.12) v1(34.67,77.98) v1(35.31,153.49) v1(35.69,82.55) v1(35.69,81.41) v1(35.69,80.26) v1(35.69,79.12) v1(35.69,77.98) v1(35.86,148.44) v1(36.09,54.99) v1(36.25,110.74) v1(36.25,69.16) v1(36.63,114.91) v1(36.58,82.55) v1(36.58,81.41) v1(36.58,80.26) v1(36.58,79.12) v1(36.58,77.98) v1(36.68,165.05) v1(36.8,160.27) v1(36.93,1.35) v1(36.96,178.61) v1(37.21,64.97) v1(37.52,156.46) v1(38.4,148.44) v1(38.38,58.04) v1(38.49,174.51) v1(38.47,159.74) v1(38.91,163.08) v1(38.91,151.05) v1(39.17,114.91) v1(39.5,178.61) v1(39.85,153.75) v1(40.49,69.42) v1(40.93,156.85) v1(40.94,148.44) v1(41,52.63) v1(41.17,65.18) v1(41.45,160.89) v1(41.76,177.23) v1(41.8,174.61) v1(41.76,107.24) v1(42.04,178.61) v1(42.01,1.35) v1(43.31,3.99) v1(43.36,150.95) v1(43.48,148.44) v1(43.73,154.72) v1(43.87,65.66) v1(44.58,178.61) v1(44.55,1.35) v1(44.82,177.18) v1(44.96,164.11) v1(45.21,69.57) v1(45.31,54.81) v1(45.9,58.32) v1(46.02,148.44) v1(46.13,173.35) v1(46.16,152.59) v1(46.63,163.37) v1(46.76,166.75) v1(47.12,178.61) v1(47.09,1.35) v1(47.47,38.61) v1(47.73,86.49) v1(47.68,3.89) v1(47.85,95.38) v1(48.23,79.81) v1(48.26,89.92) v1(48.34,52.17) v1(48.56,148.44) v1(48.64,88.37) v1(48.59,42.62) v1(48.74,93.7) v1(48.77,114.91) v1(49.2,98.42) v1(49.63,1.35) v1(49.66,178.61) v1(49.73,62.76) v1(49.78,169.88) v1(49.94,83.49) v1(50.7,94.08) v1(50.7,74.45) v1(50.75,57.73) v1(50.85,148.44) v1(50.85,145.9) v1(50.85,143.36) v1(50.85,140.82) v1(50.85,138.28) v1(50.85,135.74) v1(50.85,133.2) v1(50.85,130.66) v1(50.85,128.12) v1(50.85,125.58) v1(50.88,123.27) v1(50.88,120.8) v1(50.88,118.26) v1(50.85,115.67) v1(51.64,30.94) v1(52.2,178.61) v1(52.32,101.4) v1(52.78,99.31) v1(53.49,42.82) v1(53.62,92.99) v1(53.62,87.68) v1(53.87,57.78) v1(54.03,54.84) v1(54.13,79.45) v1(54.23,75.77) v1(54.2,35.51) v1(54.33,49.4) v1(54.38,68.55) v1(54.48,62.1) v1(54.74,178.61) v1(54.71,1.35) v1(56.59,178.61) v1(56.62,176.38) v1(56.62,173.84) v1(56.62,171.3) v1(56.62,168.76) v1(56.62,166.22) v1(56.62,163.68) v1(56.62,161.14) v1(56.62,158.6) v1(56.62,156.06) v1(56.62,153.52) v1(56.62,150.98) v1(56.62,148.44) v1(56.64,146.05) v1(56.64,143.51) v1(56.64,140.97) v1(56.64,138.43) v1(56.64,135.89) v1(56.64,133.35) v1(56.64,130.81) v1(56.64,128.27) v1(56.64,125.73) v1(56.64,123.19) v1(56.64,120.65) v1(56.64,118.11) v1(56.64,115.57) v1(56.64,113.03) v1(56.64,110.49) v1(56.64,107.95) v1(56.64,105.41) v1(56.64,102.87) v1(56.64,100.33) v1(56.64,97.79) v1(56.64,95.25) v1(56.64,92.71) v1(56.64,90.17) v1(56.64,87.63) v1(56.64,85.09) v1(56.64,82.55) v1(56.64,80.01) v1(56.64,77.47) v1(56.64,74.93) v1(56.62,72.24) v1(56.62,69.7) v1(56.62,67.16) v1(56.62,64.62) v1(56.62,62.08) v1(56.62,59.54) v1(56.62,57) v1(56.62,54.46) v1(56.62,51.92) v1(56.62,49.38) v1(56.62,46.84) v1(56.62,44.3) v1(56.62,41.76) v1(56.62,39.22) v1(56.62,36.68) v1(56.62,34.14) v1(56.62,31.6) v1(56.62,29.06) v1(56.62,26.52) v1(56.62,23.98) v1(56.62,21.44) v1(56.62,18.9) v1(56.62,16.36) v1(56.62,13.82) v1(56.62,11.28) v1(56.62,8.74) v1(56.62,6.2) v1(56.62,3.66) v1(56.62,1.37)
